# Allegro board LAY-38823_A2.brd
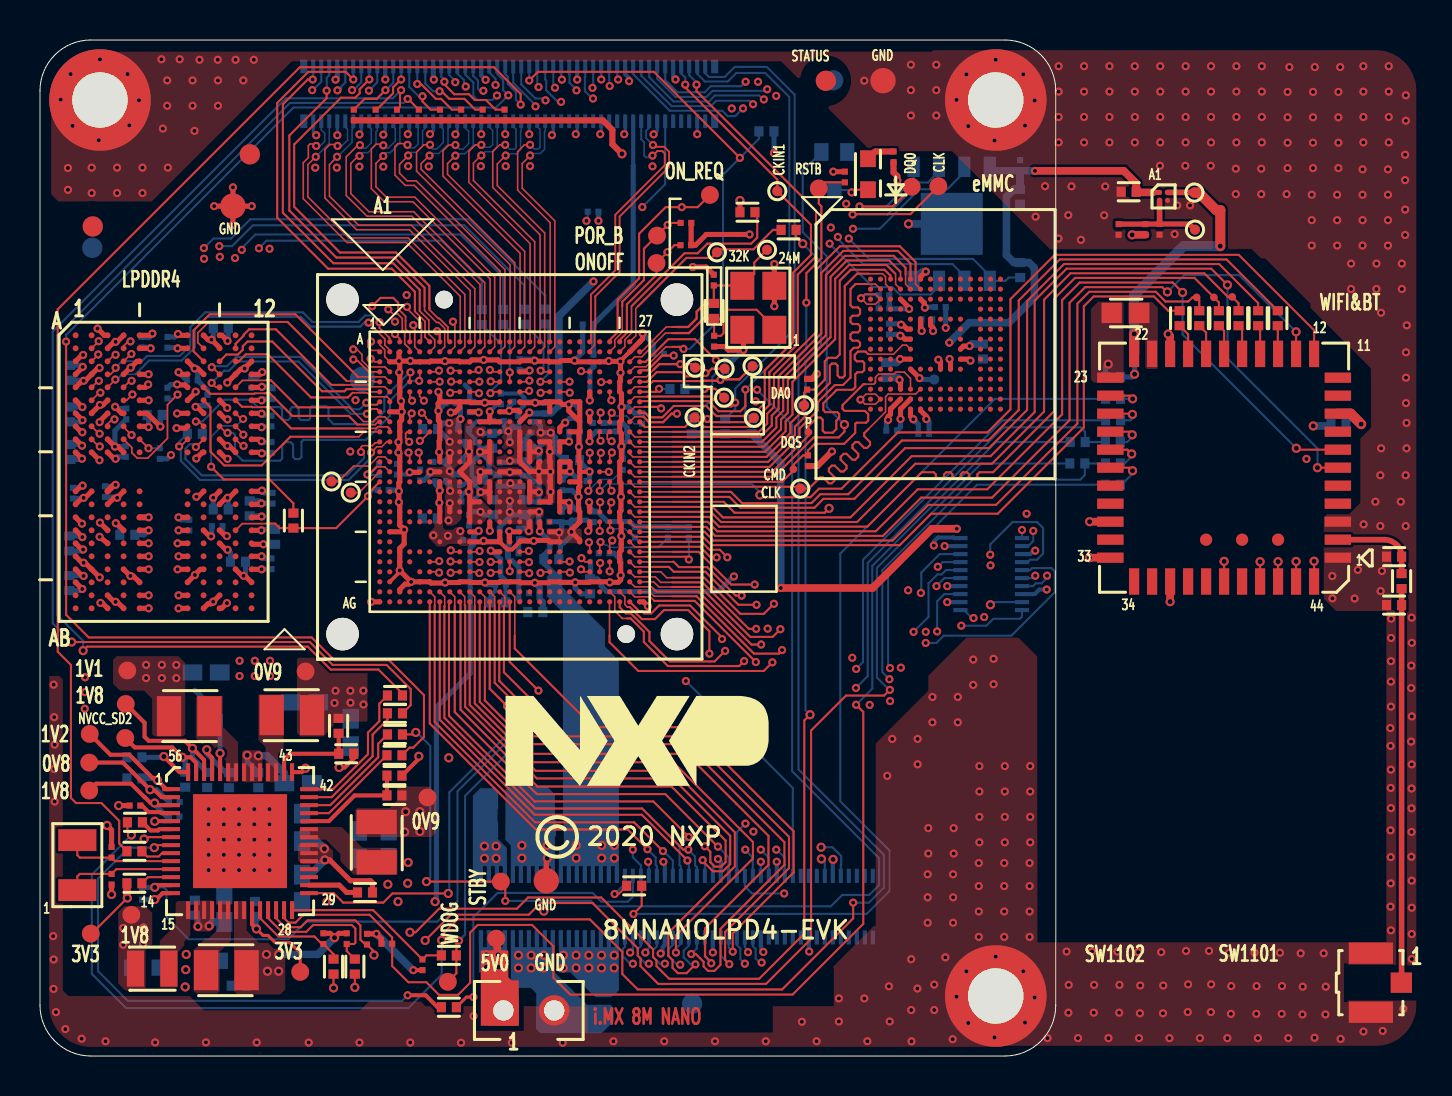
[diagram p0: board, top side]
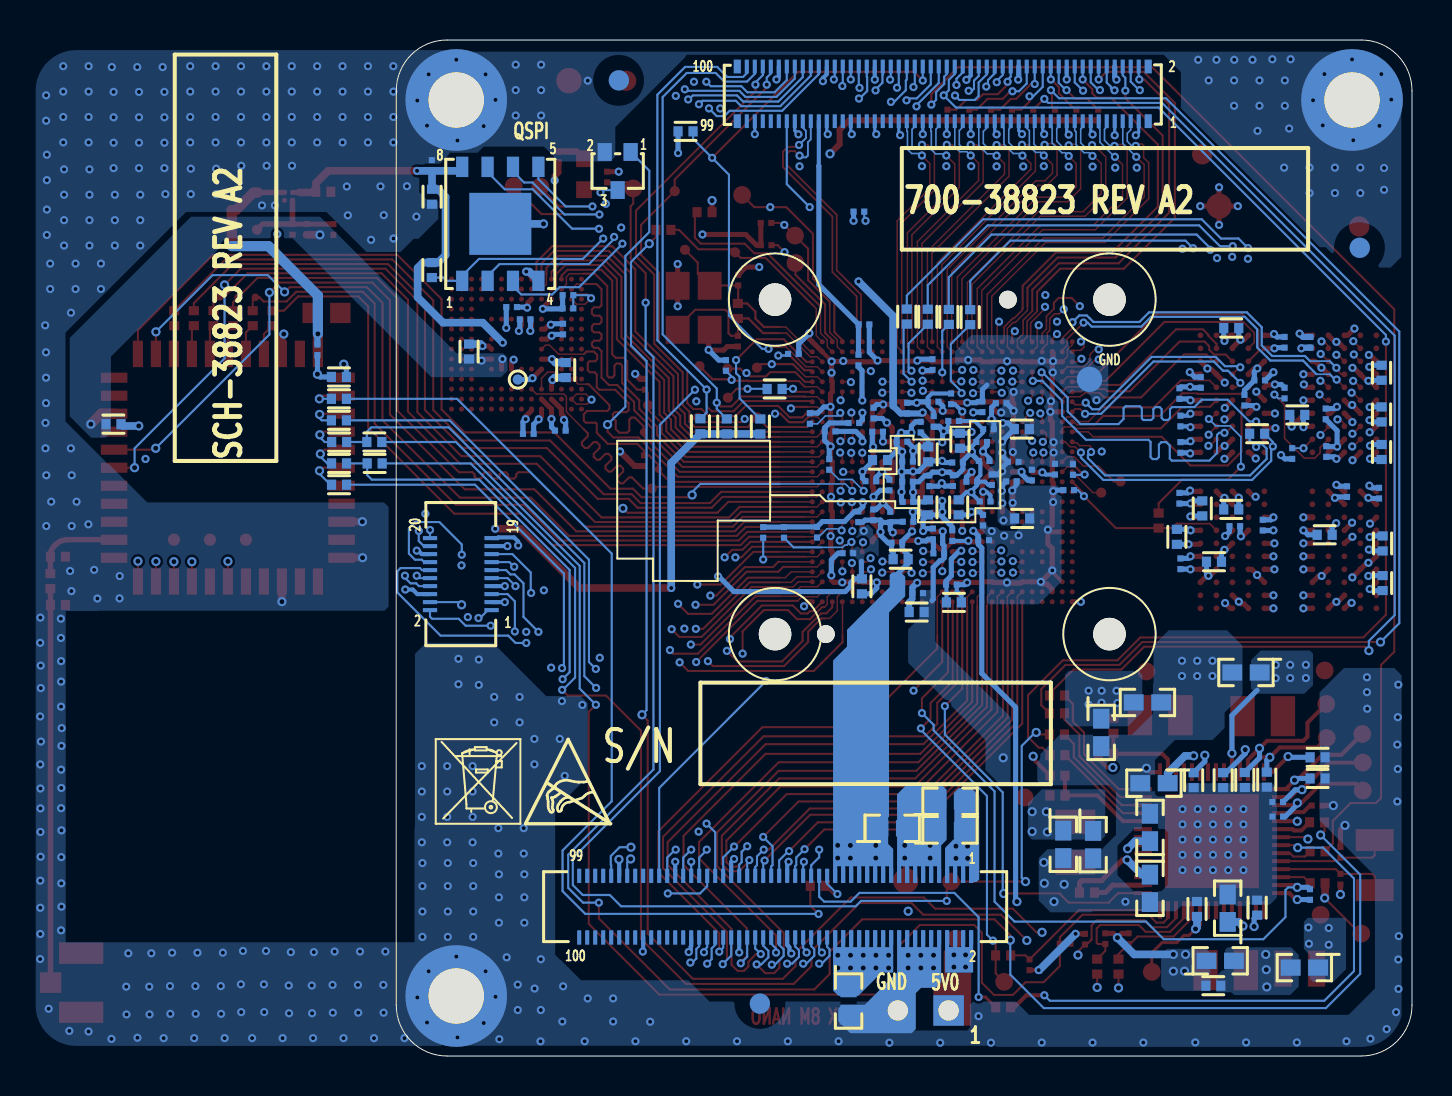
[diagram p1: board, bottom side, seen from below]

Outline 50.8 x 50.8 mm; copper layers: TOP, L2_GND, L3_IN1, L4_PWR_1, L5_PWR_2, BOTTOM. Coordinates in mm from the lower left corner of the outline.
Outline path: 0,48.26 0,2.54 arc(0.74,0.74) 2.54,0 48.26,0 arc(50.06,0.74) 50.8,2.54 50.8,48.26 arc(50.06,50.06) 48.26,50.8 2.54,50.8 arc(0.74,50.06) 0,48.26

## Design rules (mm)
constraint set DEFAULT: min track width 0.104
net group DDR-DATA0: nets DRAM_DQ06 DRAM_DQ07
net group DIFFPAIR5: nets USB1_DN USB1_DP
net group DIFFPAIR9: nets DSI_DN3 DSI_DP3
net group DIFFPAIR10: nets DSI_DN2 DSI_DP2
net group DIFFPAIR11: nets DSI_CKN DSI_CKP
net group DIFFPAIR12: nets DSI_DN1 DSI_DP1
net group DIFFPAIR13: nets DSI_DN0 DSI_DP0
net group DIFFPAIR19: nets CSI_DN0 CSI_DP0
net group DIFFPAIR20: nets CSI_DN1 CSI_DP1
net group DIFFPAIR21: nets CSI_CKN CSI_CKP
net group DIFFPAIR22: nets CSI_DN2 CSI_DP2
net group DIFFPAIR23: nets CSI_DN3 CSI_DP3
net group DDR-ADDRESS: nets DRAM_NRESET
net group M-DDR-DATA0: nets DRAM_DMI0 DRAM_DQ00 DRAM_DQ01 DRAM_DQ02 DRAM_DQ03 DRAM_DQ04 DRAM_DQ05 DRAM_SDQS0_C DRAM_SDQS0_T
net group M-DDR-DATA1: nets DRAM_DMI1 DRAM_DQ08 DRAM_DQ09 DRAM_DQ10 DRAM_DQ11 DRAM_DQ12 DRAM_DQ13 DRAM_DQ14 DRAM_DQ15 DRAM_SDQS1_C DRAM_SDQS1_T
net group M-EMMC: nets SD3_DATA1 SD3_DATA2 SD3_DATA3 SD3_DATA4 SD3_DATA5 SD3_DATA6 SD3_DATA7 SD3_STROBE
net group M-LPDDR-ADDRESS: nets DRAM_CA0_A DRAM_CA1_A DRAM_CA2_A DRAM_CA3_A DRAM_CA4_A DRAM_CA5_A DRAM_CK_C_A DRAM_CK_T_A DRAM_NCS0_A DRAM_NCS1_A
net group M-SD1: nets SD1_CLK SD1_CMD SD1_DATA0 SD1_DATA1 SD1_DATA2 SD1_DATA3
net group M-SD2: nets SD2_CLK SD2_CMD SD2_DATA0 SD2_DATA1 SD2_DATA2 SD2_DATA3

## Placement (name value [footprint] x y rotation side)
BH1  MOUNTING HOLE  [GNDPOINT256]  47.8 47.8 0 top
BH2  MOUNTING HOLE  [GNDPOINT256]  47.8 3 0 top
BH3  MOUNTING HOLE  [GNDPOINT256]  3 47.8 0 top
C1  0.22UF  [0201_CC]  22.93 31.75 180 bottom
C2  2.2uF  [0402_CC]  27.51 23.48 270 bottom
C3  0.22UF  [0201_CC]  26.94 27.06 270 bottom
C5  0.22UF  [0201_CC]  23.05 32.86 90 bottom
C6  0.22UF  [0201_CC]  25.76 25.66 0 bottom
C8  0.22UF  [0201_CC]  21.49 32.46 90 bottom
C9  0.22UF  [0201_CC]  29.11 31.23 0 bottom
C13  4.7uF  [0402_CC]  4.72 14.93 180 bottom
C15  1uF  [0201_CC]  25.21 27.71 180 bottom
C16  1uF  [0201_CC]  22.73 29.67 180 bottom
C17  0.22UF  [0201_CC]  27.69 26.96 270 bottom
C20  10uF  [0402_CC]  22.61 30.76 270 bottom
C21  0.22UF  [0201_CC]  23.04 23.57 180 bottom
C23  0.22UF  [0201_CC]  26.09 26.94 270 bottom
C30  0.22UF  [0201_CC]  26.93 32.15 90 bottom
C33  10uF  [0402_CC]  24.21 27.43 90 bottom
C35  1uF  [0201_CC]  22.96 28.77 90 bottom
C36  1uF  [0201_CC]  23.96 26.1 270 bottom
C48  1uF  [0201_CC]  21.45 26.79 270 bottom
C54  1uF  [0201_CC]  22.02 28.71 180 bottom
C55  10uF  [0402_CC]  22.67 27.43 90 bottom
C61  1uF  [0201_CC]  21.35 27.73 0 bottom
C65  1uF  [0201_CC]  23.92 31.73 90 bottom
C74  1uF  [0201_CC]  21.4 29.75 0 bottom
C78  1uF  [0201_CC]  21.52 30.7 0 bottom
C88  10uF  [0402_CC]  19.5 26.88 180 bottom
C89  10uF  [0402_CC]  19.51 31.35 180 bottom
C90  1uF  [0201_CC]  21.01 28.82 270 bottom
C91  1uF  [0201_CC]  19.01 29.05 90 bottom
C92  1uF  [0201_CC]  19.94 29.71 180 bottom
C93  1uF  [0201_CC]  20.03 28.73 180 bottom
C94  1uF  [0201_CC]  20.55 32.64 180 bottom
C95  1uF  [0201_CC]  21.18 31.34 0 bottom
C99  0.22UF  [0201_CC]  23.67 25.13 0 bottom
C100  0.22UF  [0201_CC]  23.95 32.71 0 bottom
C101  0.22UF  [0201_CC]  26.13 28.55 270 bottom
C104  0.22UF  [0201_CC]  27.07 28.74 0 bottom
C105  10uF  [0402_CC]  1.47 25.63 90 bottom
C106  10uF  [0402_CC]  11.76 25.96 90 bottom
C108  10uF  [0402_CC]  1.52 32.08 270 bottom
C109  10uF  [0402_CC]  4.37 26.06 0 bottom
C110  10uF  [0402_CC]  9.04 27.33 0 bottom
C111  10uF  [0402_CC]  9.9 24.71 0 bottom
C112  10uF  [0402_CC]  5.74 32.05 0 bottom
C113  10uF  [0402_CC]  10.49 27.38 90 bottom
C114  0.22UF  [0201_CC]  7.62 33.78 0 bottom
C115  10uF  [0402_CC]  1.52 30.2 90 bottom
C117  10uF  [0402_CC]  1.52 34.16 270 bottom
C118  10uF  [0402_CC]  9.04 36.4 0 bottom
C119  10uF  [0402_CC]  1.47 23.65 270 bottom
C121  4.7uF  [0402_CC]  64.94 31.59 180 bottom
C122  4.7uF  [0402_CC]  53.67 33.95 0 bottom
C123  12pF  [0201_CC]  33.7 38.79 90 top
C124  12pF  [0201_CC]  33.71 35.74 270 top
C127  4.7uF  [0402_CC]  47.16 35.22 90 bottom
C128  0.22UF  [0201_CC]  42.46 36.35 270 bottom
C129  0.22UF  [0201_CC]  44.35 36.83 0 bottom
C130  10uF  [0402_CC]  42.33 34.3 90 bottom
C131  0.22UF  [0201_CC]  45.03 37.45 0 bottom
C132  0.22UF  [0201_CC]  44.2 31.11 0 bottom
C133  0.22UF  [0201_CC]  42.59 31.27 0 bottom
C136  0.22UF  [0201_CC]  42.21 38.04 0 bottom
C137  1uF  [0201_CC]  42.21 37.38 0 bottom
C138  0.22UF  [0201_CC]  49.02 44.53 90 bottom
C139  10uF  [0402_CC]  49.01 42.96 270 bottom
C146  4.7uF  [0402_CC]  54.45 43.21 180 top
C148  0.22UF  [0201_CC]  55.99 41.33 270 top
C234  4.7uF  [0402_CC]  26.61 29.8 180 bottom
C235  0.22UF  [0201_CC]  25.51 30.71 180 bottom
C241  0.22UF  [0201_CC]  26.73 31.21 0 bottom
C244  0.22UF  [0201_CC]  25.25 32.39 90 bottom
C245  18pF  [0201_CC]  29.14 29.58 90 bottom
C247  10uF  [0402_CC]  24.2 30.08 90 bottom
C248  1uF  [0201_CC]  25.2 26.71 0 bottom
C251  1uF  [0201_CC]  22.99 26.02 270 bottom
C253  1uF  [0201_CC]  24.14 28.76 90 bottom
C254  1uF  [0201_CC]  25.23 29.72 180 bottom
C255  1uF  [0201_CC]  25.23 28.71 180 bottom
C256  1uF  [0201_CC]  24.57 31.44 270 bottom
C260  4.7uF  [0402_CC]  25.57 24.84 0 bottom
C264  0.22UF  [0201_CC]  21.42 25.79 180 bottom
C265  10uF  [0402_CC]  24.77 22.2 0 bottom
C266  10uF  [0402_CC]  22.91 22.68 180 bottom
C267  1uF  [0201_CC]  17.86 29.34 90 bottom
C268  2200PF  [0201_CC]  23.98 34.57 90 bottom
C272  1uF  [0402_CC]  9.45 13.79 270 bottom
C273  1.0UF  [0402_CC]  10.75 7.35 270 bottom
C274  1uF  [0201_CC]  4.75 12.52 0 top
C275  22uF  [CC0603]  13.23 17.68 180 bottom
C276  1.0UF  [0402_CC]  9.94 3.51 180 bottom
C279  10uF  [CC0603]  13.1 11.43 90 bottom
C281  10uF  [CC0603]  13.11 8.38 270 bottom
C283  22uF  [CC0603]  17.44 10.58 270 bottom
C285  22uF  [CC0603]  15.54 16.18 270 bottom
C287  22uF  [CC0603]  15.95 10.57 270 bottom
C295  10uF  [CC0603]  9.22 7.39 90 bottom
C298  18pF  [0201_CC]  3.58 10.18 90 top
C299  18pF  [0201_CC]  3.58 8.84 270 top
C301  10uF  [CC0603]  12.91 13.64 0 bottom
C302  4.7uF  [0402_CC]  7.75 7.42 90 bottom
C311  22uF  [CC0603]  9.59 4.76 180 bottom
C317  22uF  [CC0603]  5.38 4.42 0 bottom
C318  22uF  [CC0603]  8.3 19.18 0 bottom
C333  1uF  [0201_CC]  6.71 11.97 0 bottom
C337  1uF  [0201_CC]  6.72 12.7 0 bottom
C351  1uF  [0402_CC]  4.72 13.88 180 bottom
C363  2.2uF  [0402_CC]  8.36 13.8 270 bottom
C365  1uF  [0402_CC]  7.26 13.82 270 bottom
C370  0.22UF  [0201_CC]  8.86 26.49 0 bottom
C371  0.22UF  [0201_CC]  4.32 32.1 270 bottom
C372  0.22UF  [0201_CC]  11.63 33.12 90 bottom
C373  0.22UF  [0201_CC]  11.58 30.43 90 bottom
C374  0.22UF  [0201_CC]  11.58 24.61 90 bottom
C375  0.22UF  [0201_CC]  3.25 28.22 270 bottom
C376  0.22UF  [0201_CC]  4.29 30.23 90 bottom
C378  0.22UF  [0201_CC]  11.63 27.89 270 bottom
C379  0.22UF  [0201_CC]  11.58 31.75 90 bottom
C380  0.22UF  [0201_CC]  10.56 33.68 270 bottom
C381  0.22UF  [0201_CC]  1.65 28.14 270 bottom
C382  0.22UF  [0201_CC]  7.47 26.54 270 bottom
C384  0.22UF  [0201_CC]  8.38 32.79 90 bottom
C391  1uF  [0201_CC]  27.91 31.65 0 bottom
C392  0.22UF  [0201_CC]  28.21 25.14 0 bottom
C393  0.22UF  [0201_CC]  27.41 36.58 180 bottom
C400  0.22UF  [0201_CC]  24.72 23.14 0 bottom
C401  10uF  [CC0603]  23.1 12.74 180 bottom
C402  10uF  [CC0603]  23.1 11.3 180 bottom
C403  22uF  [CC0603]  26 11.39 180 bottom
C404  22uF  [CC0603]  28.18 2.75 270 bottom
C453  4.7uF  [0402_CC]  10.92 13.79 270 bottom
C454  1uF  [0201_CC]  54.74 35.31 270 bottom
C455  10pF  [0402_CC]  68.1 23.74 270 top
C456  10pF  [0402_CC]  67.72 24.97 180 top
C457  10pF  [0402_CC]  67.72 22.54 180 top
D1  LED GREEN  [LED_0603]  41.41 44.09 270 top
J1  MXC3N2001  [CON_3_UFL_R_SMT]  66.56 3.67 270 top
J4  DF40C-100DP-0.4V(51)  [CON100_0P4_21P7X2P05_SM]  23.47 48.11 0 bottom
J5  DF40C-100DS-0.4V(51)  [CON100_0P4_22P8X3P1_SM]  31.85 7.47 0 bottom
J6  HDR 1X2 TH  [HDR_1X2]  23.18 2.28 90 top
J7  DF40C-20DS-0.4V(51)  [CON20_0P4_6P8X3P1_SM]  47.57 24.1 90 bottom
L1  2.2uH  [IND_0603A]  54.29 37.15 180 top
L5  0.47uH  [IND_SPH2520]  12.6 17.04 0 top
L6  0.47uH  [IND_SPH2520]  16.84 10.69 90 top
L11  0.47uH  [IND_SPH2520]  9.32 4.29 0 top
L13  0.47uH  [IND_2016A]  5.61 4.37 180 top
L15  0.47uH  [IND_SPH2520]  7.47 16.99 180 top
NOREF  -  []  7.41 7.29 0 top
NOREF#2  -  []  1.78 22.38 0 top
NOREF#3  -  []  23.3 13.51 0 top
NOREF#4  -  [unnamed#2]  2.64 41.48 0 top
NOREF#5  -  []  -264.82 291.64 0 top
NOREF#6  -  []  53.53 24.92 90 top
NOREF#7  -  []  6.51 0.24 0 top
NOREF#8  -  []  11.23 21.91 90 top
NOREF#9  -  []  46.03 25.9 0 top
NOREF#10  -  []  27.36 2.21 0 top
NOREF#11  -  []  641.81 -152.03 0 top
NOREF#12  -  []  54.72 35.11 0 top
NOREF#13  -  [unnamed#2]  39.3 48.76 0 top
NOREF#14  -  []  23.49 29.21 0 top
NOREF#15  -  []  38.33 6.17 0 top
NOREF#16  -  []  22.05 9.01 0 top
NOREF#17  -  []  10.58 35.38 90 top
NOREF#18  -  []  1.13 21.91 0 top
NOREF#19  -  []  56.39 42.78 90 top
NOREF#20  -  []  12.61 7.29 90 top
NOREF#21  -  []  54.72 35.11 0 top
NOREF#22  -  []  55.99 42.78 0 top
NOREF#23  -  []  1.78 22.38 0 top
NOREF#24  -  []  -292.82 -210.12 0 top
NOREF#25  -  []  53.53 33.92 0 top
NOREF#26  -  []  279.89 66.11 0 top
NOREF#27  -  []  25.87 10.93 0 top
NOREF#28  -  []  53.17 35.47 0 top
NOREF#29  -  [unnamed#2]  10.49 45.08 90 top
NOREF#30  -  []  46.03 22.3 90 top
NOREF#31  -  []  46.03 22.3 90 top
NOREF#32  -  []  22.85 9.01 0 top
NOREF#33  -  []  10.58 22.38 90 top
NOREF#34  -  []  13.46 8.14 90 top
NOREF#35  -  []  -25.43 -42.54 0 top
NOREF#36  -  []  53.53 33.02 90 top
NOREF#37  -  []  -38.84 -146.35 0 top
NOREF#38  -  []  59.22 29.42 0 top
NOREF#39  -  []  56.59 42.58 90 top
NOREF#40  -  []  43.25 5.9 90 top
NOREF#41  -  []  6.56 8.14 0 top
NOREF#42  -  []  46 27.5 0 top
NOREF#43  -  []  55.79 42.58 0 top
NOREF#44  -  []  6.51 0.24 90 top
NOREF#45  -  []  46 20.7 90 top
NOREF#46  -  []  53.17 23.37 90 top
NOREF#47  -  []  20.45 9.04 0 top
NOREF#48  -  []  41.65 5.93 90 top
NOREF#49  -  []  54.72 23.73 90 top
NOREF#50  -  [unnamed#3]  23.49 29.46 270 top
NOREF#51  -  []  13.46 12.94 90 top
NOREF#52  -  []  0.16 0.59 0 top
NOREF#53  -  []  58.32 25.82 0 top
NOREF#54  -  []  -8.88 -33.57 0 top
NOREF#55  -  []  58.32 25.82 90 top
NOREF#56  -  []  59.22 29.42 0 top
NOREF#57  -  []  41.62 6.72 90 top
NOREF#58  -  []  7.41 7.29 0 top
NOREF#59  -  [unnamed#2]  2.61 40.41 180 bottom
NOREF#60  -  [unnamed#2]  39.67 48.78 180 bottom
NOREF#61  -  [unnamed#2]  32.61 2.62 270 bottom
Q1  NX3008NBKW,115  [SC70_3]  39.73 44.25 0 bottom
QZ2  32.768KHZ  [XTAL2-3P2X1P5-SM]  1.87 9.54 90 top
R4  10K  [0201_CC]  17.17 28.29 180 bottom
R5  240 OHM  [0201_CC]  5.08 35.69 90 bottom
R7  240 OHM  [0201_CC]  16.96 29.32 270 bottom
R8  150  [0402_CC]  7.75 31.11 0 bottom
R10  4.7K  [0201_CC]  17.85 47.05 90 top
R11  4.7K  [0201_CC]  18.95 47.05 90 top
R12  4.7K  [0201_CC]  15.69 47.05 90 top
R13  4.7K  [0201_CC]  16.79 47.05 90 top
R14  4.7K  [0201_CC]  20.01 47.05 90 top
R15  4.7K  [0201_CC]  21.06 47.05 90 top
R16  4.7K  [0201_CC]  22.14 47.05 90 top
R17  4.7K  [0201_CC]  23.23 47.05 90 top
R18  10K  [0201_CC]  34.31 34.53 90 bottom
R20  100K  [0201_CC]  32.31 41.66 180 top
R21  100K  [0201_CC]  32.3 40.54 180 top
R23  10K  [0201_CC]  30.94 35.1 180 bottom
R26  510K  [0402_CC]  33.71 37.25 270 top
R27  50 OHM  [0402_CC]  31.88 33.35 0 bottom
R29  200  [0201_CC]  27.66 42.22 0 bottom
R37  10K  [0402_CC]  49.02 39.3 270 bottom
R47  10K  [0402_CC]  34.27 31.48 270 bottom
R48  0  [0402_CC]  17.75 17.13 180 top
R51  0  [0402_CC]  17.73 15.04 180 top
R52  0  [0402_CC]  17.75 16.08 180 top
R54  0  [0402_CC]  17.75 18.02 180 top
R55  0  [0402_CC]  20.45 5.03 180 top
R61  100K  [0201_CC]  5.1 8.08 270 bottom
R77  10K  [0402_CC]  36.33 46.23 0 bottom
R78  10K  [0402_CC]  32.59 31.48 270 bottom
R79  10K  [0402_CC]  35.59 31.49 270 bottom
R100  0  [0402_CC]  37.44 41.31 180 top
R102  100K  [0201_CC]  40.25 43.95 270 top
R103  100K  [0201_CC]  30.11 31.88 90 bottom
R106  100K  [0201_CC]  19.13 4.56 90 top
R108  30K  [0201_CC]  27.68 34.8 90 bottom
R111  0  [0402_CC]  4.75 11.68 180 top
R113  0  [0402_CC]  35.38 42.19 0 top
R114  0  [0402_CC]  4.72 10.24 180 top
R115  0  [0402_CC]  53.67 32.86 0 bottom
R116  0  [0402_CC]  29.72 8.51 180 top
R117  10K  [0201_CC]  38.36 33.59 270 top
R118  10K  [0201_CC]  38.41 29.76 90 top
R119  10K  [0201_CC]  31.41 26.18 270 bottom
R120  10K  [0201_CC]  29.76 26.19 270 bottom
R121  10K  [0201_CC]  6.37 33.15 270 bottom
R125  1K  [0201_CC]  42.69 44.96 90 top
R127  0  [0402_CC]  20.45 2.44 180 top
R129  0  [0402_CC]  53.66 28.56 180 bottom
R130  0  [0402_CC]  53.66 29.63 180 bottom
R131  0  [0402_CC]  53.66 30.7 180 bottom
R132  0  [0402_CC]  53.67 31.78 180 bottom
R133  4.7K  [0201_CC]  32.45 26.18 270 bottom
R137  0  [0402_CC]  4.72 8.64 0 top
R153  10K  [0201_CC]  55.28 41.33 90 top
R157  240 OHM  [0201_CC]  6.37 35.69 90 bottom
R158  10K  [0201_CC]  5.99 30.12 90 bottom
R191  0  [0402_CC]  15.31 15.11 0 top
R192  0  [0402_CC]  14.93 16.51 270 top
R193  0  [0402_CC]  17.73 13.03 180 top
R194  0  [0402_CC]  17.73 14.02 0 top
R195  0  [0402_CC]  16.25 8.18 0 top
R196  4.7K  [0201_CC]  17.35 5.61 0 top
R197  4.7K  [0201_CC]  16.36 5.84 270 top
R198  0  [0402_CC]  51.89 30.7 180 bottom
R199  0  [0402_CC]  51.88 29.63 180 bottom
R200  4.7K  [0201_CC]  14.17 5.87 270 top
R201  4.7K  [0201_CC]  15.34 5.87 270 top
R202  0  [0402_CC]  14.68 4.47 90 top
R203  0  [0402_CC]  15.75 4.47 90 top
R204  0  [0402_CC]  12.67 26.77 270 top
R205  0  [0402_CC]  25.27 36.97 270 bottom
R206  0  [0402_CC]  22.1 36.94 270 bottom
R207  0  [0402_CC]  23.16 36.95 270 bottom
R208  0  [0402_CC]  24.22 36.96 270 bottom
R209  0  [0402_CC]  57.98 36.89 270 top
R210  0  [0402_CC]  57 36.89 270 top
R211  0  [0402_CC]  61.91 36.89 270 top
R212  0  [0402_CC]  60.92 36.89 270 top
R213  0  [0402_CC]  59.94 36.89 270 top
R214  0  [0402_CC]  58.96 36.89 270 top
R215  12K  [0201_CC]  53.94 41.33 270 top
TP2  -  [TPAD_020]  34.24 34.37 0 top
TP3  -  [TPAD_020]  34.21 32.92 0 top
TP4  -  [TPAD_020]  35.63 34.49 0 top
TP5  -  [TPAD_020]  32.76 34.42 0 top
TP6  TP_35MIL  [TESTPOINT_35MIL]  33.5 43.05 0 top
TP7  TP_35MIL  [TESTPOINT_35MIL]  30.83 39.65 180 top
TP8  TP_35MIL  [TESTPOINT_35MIL]  38.95 43.38 270 top
TP9  TP_35MIL  [TESTPOINT_35MIL]  30.86 41.02 0 top
TP10  TP_35MIL  [TESTPOINT_35MIL]  23.05 8.72 0 top
TP12  -  [TPAD_020]  57.76 41.32 0 top
TP13  -  [TPAD_020]  57.73 43.17 0 top
TP15  -  [TPAD_020]  14.58 28.73 0 top
TP16  TP_35MIL  [TESTPOINT_35MIL]  43.59 43.46 180 top
TP17  TP_35MIL  [TESTPOINT_35MIL]  44.93 43.49 180 top
TP18  -  [TPAD_020]  44.72 33.82 180 bottom
TP19  -  [TPAD_020]  35.7 31.91 0 top
TP20  -  [TPAD_020]  36.87 43.24 0 top
TP21  -  [TPAD_020]  32.74 31.93 0 top
TP22  TP_35MIL  [TESTPOINT_35MIL]  13.28 19.23 0 top
TP23  TP_35MIL  [TESTPOINT_35MIL]  19.38 12.93 90 top
TP24  -  [TPAD_015]  57.84 37.93 180 top
TP25  TP_35MIL  [TESTPOINT_35MIL]  2.54 6.12 0 top
TP26  TP_35MIL  [TESTPOINT_35MIL]  4.57 7.06 0 top
TP27  TP_35MIL  [TESTPOINT_35MIL]  4.37 19.28 270 top
TP28  TP_35MIL  [TESTPOINT_35MIL]  2.46 13.27 0 top
TP29  TP_35MIL  [TESTPOINT_35MIL]  2.46 14.67 0 top
TP31  TP_35MIL  [TESTPOINT_35MIL]  2.49 16.1 0 top
TP32  TP_35MIL  [TESTPOINT_35MIL]  4.29 17.6 0 top
TP33  TP_35MIL  [TESTPOINT_35MIL]  4.27 15.9 0 top
TP34  -  [TPAD_020]  38.02 28.37 0 top
TP35  -  [TPAD_015]  37.68 29.34 0 top
TP36  -  [TPAD_020]  38.21 32.54 0 top
TP38  -  [TPAD_020]  36.36 40.31 0 top
TP39  -  [TPAD_020]  33.85 40.18 0 top
TP40  -  [TPAD_015]  38.43 31.19 0 top
TP44  -  [TPAD_050]  9.65 42.49 0 top
TP45  -  [TPAD_050]  25.32 8.76 0 top
TP46  -  [TPAD_050]  42.16 48.77 0 top
TP47  -  [TPAD_050]  16.13 33.83 180 bottom
TP51  TP_35MIL  [TESTPOINT_35MIL]  22.82 5.87 0 top
TP53  TP_35MIL  [TESTPOINT_35MIL]  20.4 3.71 0 top
TP58  -  [TPAD_020]  15.54 28.17 0 top
TP66  -  [TPAD_015]  58.71 37.93 180 top
TP67  -  [TPAD_015]  59.62 37.96 180 top
TP68  TP_35MIL  [TESTPOINT_35MIL]  13.01 4.21 0 top
U1  MIMX8MN6DVTJZAA  [BGA486_0P5_14X14]  23.49 29.21 0 top
U2  -  [BGA200_0P65X0P8_10P1X14P6]  6.18 29.21 0 top
U4  SDINBDG4-32G-I1  [FBGA153_0P5_11P5X13]  44.79 35.59 0 top
U5  MT25QU256ABA1EW7-0SIT  [DFN8_1P27_6X5MM_3P1]  45.6 41.61 90 bottom
U7  ADP191ACBZ-R7  [WLCSP4_0P4_0P8X0P8_SMDP]  56.19 42.98 0 top
U8  PCA9450BHN  [HVQFN56_0P4_7X7_EP4P7MM]  10.01 10.74 0 top
U9  AW-CM358SM  [MODULE_WIFI_0P9_12X12_47PIN_A]  59.22 29.42 180 top
Y1  24MHZ  [XTLOSC4_3P2X2P5MM_SM]  35.93 37.41 90 top

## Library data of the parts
BH1-BH3 = MOUNT_HOLE
C1-C3 C5 C6 C8 C9 C13 C15-C17 C20 C21 C23 C30 C33 C35 C36 C48 C54 C55 C61 C65 C74 C78 C88-C95 C99-C101 C104-C106 C108-C115 C117-C119 C121-C124 C127-C133 C136-C139 C146 C148 C234 C235 C241 C244 C245 C247 C248 C251 C253-C256 C260 C264-C268 C272-C276 C279 C281 C283 C285 C287 C295 C298 C299 C301 C302 C311 C317 C318 C333 C337 C351 C363 C365 C370-C376 C378-C382 C384 C391-C393 C400-C404 C453-C457 = CAP_NP
D1 = LED
J1 = UFL
J4 J5 = HDR_2X50_M
J6 = CONN_HDR_2X1
J7 = CONN_HDR_10X2
L1 L13 = INDUCTOR
L5 L6 L11 L15 = INDUCTOR: tolerance: 20%
Q1 = NMOS_NX3008NBK
QZ2 = XTAL
R4 R5 R7 R8 R10-R18 R20 R21 R23 R26 R27 R29 R37 R48 R51 R52 R54 R55 R61 R100 R102 R103 R106 R108 R113-R121 R125 R127 R133 R137 R153 R157 R158 R191-R203 R215 = RES
R47 R77-R79 = RES: tolerance: 5%
R111 R129-R132 R204-R214 = RES: tolerance: 1%
TP2-TP5 TP12 TP13 TP15 TP18-TP21 TP24 TP34-TP36 TP38-TP40 TP44-TP47 TP58 TP66 TP67 = TESTLOOP
TP6-TP10 TP16 TP17 TP22 TP23 TP25-TP29 TP31-TP33 TP51 TP53 TP68 = T POINT R: Tolerance: TOLERANCE; User Part Number: 510-75618
U1 = MIMX8NN_BGA486P
U2 = C1612PC2WDGTKR-U_BGA200P
U4 = SDINBDG4-16G_VFBGA_153P
U5 = MT25QL256ABA1EW9_9P
U7 = ADP199_4P
U8 = PCA9450_HVQFN56P_A
U9 = AW_CM358SM
Y1 = XTAL_13

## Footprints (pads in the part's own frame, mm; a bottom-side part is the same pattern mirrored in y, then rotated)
0201_CC
  rect 0.305x0.305 smd: 1(-0.267,0) 2(0.267,0)
0402_CC
  rect 0.457x0.508 smd: 1(-0.375,0) 2(0.375,0)
BGA200_0P65X0P8_10P1X14P6
  round 0.292 smd: A1(-4.4,6.825) A2(-3.6,6.825) A3(-2.8,6.825) A4(-2,6.825) A5(-1.2,6.825) A8(1.2,6.825) A9(2,6.825) A10(2.8,6.825) A11(3.6,6.825) A12(4.4,6.825) AA1(-4.4,-6.175) AA2(-3.6,-6.175) AA3(-2.8,-6.175) AA4(-2,-6.175) AA5(-1.2,-6.175) AA8(1.2,-6.175) AA9(2,-6.175) AA10(2.8,-6.175) AA11(3.6,-6.175) AA12(4.4,-6.175) AB1(-4.4,-6.825) AB2(-3.6,-6.825) AB3(-2.8,-6.825) AB4(-2,-6.825) AB5(-1.2,-6.825) AB8(1.2,-6.825) AB9(2,-6.825) AB10(2.8,-6.825) AB11(3.6,-6.825) AB12(4.4,-6.825) B1(-4.4,6.175) B2(-3.6,6.175) B3(-2.8,6.175) B4(-2,6.175) B5(-1.2,6.175) B8(1.2,6.175) B9(2,6.175) B10(2.8,6.175) B11(3.6,6.175) B12(4.4,6.175) C1(-4.4,5.525) C2(-3.6,5.525) C3(-2.8,5.525) C4(-2,5.525) C5(-1.2,5.525) C8(1.2,5.525) C9(2,5.525) C10(2.8,5.525) C11(3.6,5.525) C12(4.4,5.525) D1(-4.4,4.875) D2(-3.6,4.875) D3(-2.8,4.875) D4(-2,4.875) D5(-1.2,4.875) D8(1.2,4.875) D9(2,4.875) D10(2.8,4.875) D11(3.6,4.875) D12(4.4,4.875) E1(-4.4,4.225) E2(-3.6,4.225) E3(-2.8,4.225) E4(-2,4.225) E5(-1.2,4.225) E8(1.2,4.225) E9(2,4.225) E10(2.8,4.225) E11(3.6,4.225) E12(4.4,4.225) F1(-4.4,3.575) F2(-3.6,3.575) F3(-2.8,3.575) F4(-2,3.575) F5(-1.2,3.575) F8(1.2,3.575) F9(2,3.575) F10(2.8,3.575) F11(3.6,3.575) F12(4.4,3.575) G1(-4.4,2.925) G2(-3.6,2.925) G3(-2.8,2.925) G4(-2,2.925) G5(-1.2,2.925) G8(1.2,2.925) G9(2,2.925) G10(2.8,2.925) G11(3.6,2.925) G12(4.4,2.925) H1(-4.4,2.275) H2(-3.6,2.275) H3(-2.8,2.275) H4(-2,2.275) H5(-1.2,2.275) H8(1.2,2.275) H9(2,2.275) H10(2.8,2.275) H11(3.6,2.275) H12(4.4,2.275) J1(-4.4,1.625) J2(-3.6,1.625) J3(-2.8,1.625) J4(-2,1.625) J5(-1.2,1.625) J8(1.2,1.625) J9(2,1.625) J10(2.8,1.625) J11(3.6,1.625) J12(4.4,1.625) K1(-4.4,0.975) K2(-3.6,0.975) K3(-2.8,0.975) K4(-2,0.975) K5(-1.2,0.975) K8(1.2,0.975) K9(2,0.975) K10(2.8,0.975) K11(3.6,0.975) K12(4.4,0.975) N1(-4.4,-0.975) N2(-3.6,-0.975) N3(-2.8,-0.975) N4(-2,-0.975) N5(-1.2,-0.975) N8(1.2,-0.975) N9(2,-0.975) N10(2.8,-0.975) N11(3.6,-0.975) N12(4.4,-0.975) P1(-4.4,-1.625) P2(-3.6,-1.625) P3(-2.8,-1.625) P4(-2,-1.625) P5(-1.2,-1.625) P8(1.2,-1.625) P9(2,-1.625) P10(2.8,-1.625) P11(3.6,-1.625) P12(4.4,-1.625) R1(-4.4,-2.275) R2(-3.6,-2.275) R3(-2.8,-2.275) R4(-2,-2.275) R5(-1.2,-2.275) R8(1.2,-2.275) R9(2,-2.275) R10(2.8,-2.275) R11(3.6,-2.275) R12(4.4,-2.275) T1(-4.4,-2.925) T2(-3.6,-2.925) T3(-2.8,-2.925) T4(-2,-2.925) T5(-1.2,-2.925) T8(1.2,-2.925) T9(2,-2.925) T10(2.8,-2.925) T11(3.6,-2.925) T12(4.4,-2.925) U1(-4.4,-3.575) U2(-3.6,-3.575) U3(-2.8,-3.575) U4(-2,-3.575) U5(-1.2,-3.575) U8(1.2,-3.575) U9(2,-3.575) U10(2.8,-3.575) U11(3.6,-3.575) U12(4.4,-3.575) V1(-4.4,-4.225) V2(-3.6,-4.225) V3(-2.8,-4.225) V4(-2,-4.225) V5(-1.2,-4.225) V8(1.2,-4.225) V9(2,-4.225) V10(2.8,-4.225) V11(3.6,-4.225) V12(4.4,-4.225) W1(-4.4,-4.875) W2(-3.6,-4.875) W3(-2.8,-4.875) W4(-2,-4.875) W5(-1.2,-4.875) W8(1.2,-4.875) W9(2,-4.875) W10(2.8,-4.875) W11(3.6,-4.875) W12(4.4,-4.875) Y1(-4.4,-5.525) Y2(-3.6,-5.525) Y3(-2.8,-5.525) Y4(-2,-5.525) Y5(-1.2,-5.525) Y8(1.2,-5.525) Y9(2,-5.525) Y10(2.8,-5.525) Y11(3.6,-5.525) Y12(4.4,-5.525)
BGA486_0P5_14X14
  round 0.254 smd: A1(-6.5,6.5) A2(-6,6.5) A3(-5.5,6.5) A4(-5,6.5) A5(-4.5,6.5) A6(-4,6.5) A7(-3.5,6.5) A8(-3,6.5) A9(-2.5,6.5) A10(-2,6.5) A11(-1.5,6.5) A12(-1,6.5) A13(-0.5,6.5) A14(0,6.5) A15(0.5,6.5) A16(1,6.5) A17(1.5,6.5) A18(2,6.5) A19(2.5,6.5) A20(3,6.5) A21(3.5,6.5) A22(4,6.5) A23(4.5,6.5) A24(5,6.5) A25(5.5,6.5) A26(6,6.5) A27(6.5,6.5) AA1(-6.5,-3.5) AA2(-6,-3.5) AA7(-3.5,-3.5) AA9(-2.5,-3.5) AA10(-2,-3.5) AA13(-0.5,-3.5) AA14(0,-3.5) AA15(0.5,-3.5) AA18(2,-3.5) AA19(2.5,-3.5) AA21(3.5,-3.5) AA26(6,-3.5) AA27(6.5,-3.5) AB1(-6.5,-4) AB2(-6,-4) AB3(-5.5,-4) AB4(-5,-4) AB5(-4.5,-4) AB6(-4,-4) AB9(-2.5,-4) AB10(-2,-4) AB13(-0.5,-4) AB15(0.5,-4) AB18(2,-4) AB19(2.5,-4) AB22(4,-4) AB23(4.5,-4) AB24(5,-4) AB25(5.5,-4) AB26(6,-4) AB27(6.5,-4) AC1(-6.5,-4.5) AC2(-6,-4.5) AC3(-5.5,-4.5) AC4(-5,-4.5) AC6(-4,-4.5) AC9(-2.5,-4.5) AC10(-2,-4.5) AC13(-0.5,-4.5) AC14(0,-4.5) AC15(0.5,-4.5) AC18(2,-4.5) AC19(2.5,-4.5) AC22(4,-4.5) AC24(5,-4.5) AC25(5.5,-4.5) AC26(6,-4.5) AC27(6.5,-4.5) AD1(-6.5,-5) AD2(-6,-5) AD5(-4.5,-5) AD6(-4,-5) AD9(-2.5,-5) AD10(-2,-5) AD13(-0.5,-5) AD15(0.5,-5) AD18(2,-5) AD19(2.5,-5) AD22(4,-5) AD23(4.5,-5) AD26(6,-5) AD27(6.5,-5) AE1(-6.5,-5.5) AE2(-6,-5.5) AE5(-4.5,-5.5) AE6(-4,-5.5) AE9(-2.5,-5.5) AE10(-2,-5.5) AE13(-0.5,-5.5) AE14(0,-5.5) AE15(0.5,-5.5) AE18(2,-5.5) AE19(2.5,-5.5) AE22(4,-5.5) AE23(4.5,-5.5) AE26(6,-5.5) AE27(6.5,-5.5) AF1(-6.5,-6) AF2(-6,-6) AF3(-5.5,-6) AF4(-5,-6) AF5(-4.5,-6) AF6(-4,-6) AF7(-3.5,-6) AF8(-3,-6) AF9(-2.5,-6) AF10(-2,-6) AF11(-1.5,-6) AF12(-1,-6) AF13(-0.5,-6) AF14(0,-6) AF15(0.5,-6) AF16(1,-6) AF17(1.5,-6) AF18(2,-6) AF19(2.5,-6) AF20(3,-6) AF21(3.5,-6) AF22(4,-6) AF23(4.5,-6) AF24(5,-6) AF25(5.5,-6) AF26(6,-6) AF27(6.5,-6) AG1(-6.5,-6.5) AG2(-6,-6.5) AG3(-5.5,-6.5) AG4(-5,-6.5) AG5(-4.5,-6.5) AG6(-4,-6.5) AG7(-3.5,-6.5) AG8(-3,-6.5) AG9(-2.5,-6.5) AG10(-2,-6.5) AG11(-1.5,-6.5) AG12(-1,-6.5) AG13(-0.5,-6.5) AG14(0,-6.5) AG15(0.5,-6.5) AG16(1,-6.5) AG17(1.5,-6.5) AG18(2,-6.5) AG19(2.5,-6.5) AG20(3,-6.5) AG21(3.5,-6.5) AG22(4,-6.5) AG23(4.5,-6.5) AG24(5,-6.5) AG25(5.5,-6.5) AG26(6,-6.5) AG27(6.5,-6.5) B1(-6.5,6) B2(-6,6) B3(-5.5,6) B4(-5,6) B5(-4.5,6) B6(-4,6) B7(-3.5,6) B8(-3,6) B9(-2.5,6) B10(-2,6) B11(-1.5,6) B12(-1,6) B13(-0.5,6) B14(0,6) B15(0.5,6) B16(1,6) B17(1.5,6) B18(2,6) B19(2.5,6) B20(3,6) B21(3.5,6) B22(4,6) B23(4.5,6) B24(5,6) B25(5.5,6) B26(6,6) B27(6.5,6) C1(-6.5,5.5) C2(-6,5.5) C5(-4.5,5.5) C6(-4,5.5) C9(-2.5,5.5) C10(-2,5.5) C13(-0.5,5.5) C14(0,5.5) C15(0.5,5.5) C18(2,5.5) C19(2.5,5.5) C22(4,5.5) C23(4.5,5.5) C26(6,5.5) C27(6.5,5.5) D1(-6.5,5) D2(-6,5) D5(-4.5,5) D6(-4,5) D9(-2.5,5) D10(-2,5) D13(-0.5,5) D15(0.5,5) D18(2,5) D19(2.5,5) D22(4,5) D23(4.5,5) D26(6,5) D27(6.5,5) E1(-6.5,4.5) E2(-6,4.5) E3(-5.5,4.5) E4(-5,4.5) E6(-4,4.5) E9(-2.5,4.5) E10(-2,4.5) E13(-0.5,4.5) E14(0,4.5) E15(0.5,4.5) E18(2,4.5) E19(2.5,4.5) E22(4,4.5) E24(5,4.5) E25(5.5,4.5) E26(6,4.5) E27(6.5,4.5) F1(-6.5,4) F2(-6,4) F3(-5.5,4) F4(-5,4) F5(-4.5,4) F6(-4,4) F9(-2.5,4) F10(-2,4) F13(-0.5,4) F15(0.5,4) F18(2,4) F19(2.5,4) F22(4,4) F23(4.5,4) F24(5,4) F25(5.5,4) F26(6,4) F27(6.5,4) G1(-6.5,3.5) G2(-6,3.5) G7(-3.5,3.5) G9(-2.5,3.5) G10(-2,3.5) G13(-0.5,3.5) G14(0,3.5) G15(0.5,3.5) G18(2,3.5) G19(2.5,3.5) G21(3.5,3.5) G26(6,3.5) G27(6.5,3.5) H1(-6.5,3) H2(-6,3) H10(-2,3) H13(-0.5,3) H15(0.5,3) H18(2,3) H26(6,3) H27(6.5,3) J1(-6.5,2.5) J2(-6,2.5) J3(-5.5,2.5) J4(-5,2.5) J5(-4.5,2.5) J6(-4,2.5) J7(-3.5,2.5) J10(-2,2.5) J11(-1.5,2.5) J12(-1,2.5) J13(-0.5,2.5) J14(0,2.5) J15(0.5,2.5) J16(1,2.5) J17(1.5,2.5) J18(2,2.5) J21(3.5,2.5) J22(4,2.5) J23(4.5,2.5) J24(5,2.5) J25(5.5,2.5) J26(6,2.5) J27(6.5,2.5) K1(-6.5,2) K2(-6,2) K3(-5.5,2) K4(-5,2) K5(-4.5,2) K6(-4,2) K7(-3.5,2) K8(-3,2) K9(-2.5,2) K12(-1,2) K13(-0.5,2) K15(0.5,2) K16(1,2) K19(2.5,2) K20(3,2) K21(3.5,2) K22(4,2) K23(4.5,2) K24(5,2) K25(5.5,2) K26(6,2) K27(6.5,2) L1(-6.5,1.5) L2(-6,1.5) L9(-2.5,1.5) L10(-2,1.5) L11(-1.5,1.5) L12(-1,1.5) L13(-0.5,1.5) L15(0.5,1.5) L16(1,1.5) L17(1.5,1.5) L18(2,1.5) L19(2.5,1.5) L26(6,1.5) L27(6.5,1.5) M1(-6.5,1) M2(-6,1) M9(-2.5,1) M12(-1,1) M13(-0.5,1) M14(0,1) M15(0.5,1) M16(1,1) M19(2.5,1) M26(6,1) M27(6.5,1) N1(-6.5,0.5) N2(-6,0.5) N3(-5.5,0.5) N4(-5,0.5) N5(-4.5,0.5) N6(-4,0.5) N7(-3.5,0.5) N8(-3,0.5) N9(-2.5,0.5) N10(-2,0.5) N11(-1.5,0.5) N12(-1,0.5) N13(-0.5,0.5) N15(0.5,0.5) N16(1,0.5) N17(1.5,0.5) N18(2,0.5) N19(2.5,0.5) N20(3,0.5) N21(3.5,0.5) N22(4,0.5) N23(4.5,0.5) N24(5,0.5) N25(5.5,0.5) N26(6,0.5) N27(6.5,0.5) P1(-6.5,0) P2(-6,0) P3(-5.5,0) P5(-4.5,0) P7(-3.5,0) P9(-2.5,0) P12(-1,0) P13(-0.5,0) P15(0.5,0) P16(1,0) P19(2.5,0) P21(3.5,0) P23(4.5,0) P25(5.5,0) P26(6,0) P27(6.5,0) R1(-6.5,-0.5) R2(-6,-0.5) R3(-5.5,-0.5) R4(-5,-0.5) R5(-4.5,-0.5) R6(-4,-0.5) R7(-3.5,-0.5) R8(-3,-0.5) R9(-2.5,-0.5) R10(-2,-0.5) R11(-1.5,-0.5) R12(-1,-0.5) R13(-0.5,-0.5) R15(0.5,-0.5) R16(1,-0.5) R17(1.5,-0.5) R18(2,-0.5) R19(2.5,-0.5) R20(3,-0.5) R21(3.5,-0.5) R22(4,-0.5) R23(4.5,-0.5) R24(5,-0.5) R25(5.5,-0.5) R26(6,-0.5) R27(6.5,-0.5) T1(-6.5,-1) T2(-6,-1) T9(-2.5,-1) T12(-1,-1) T13(-0.5,-1) T14(0,-1) T15(0.5,-1) T16(1,-1) T19(2.5,-1) T26(6,-1) T27(6.5,-1) U1(-6.5,-1.5) U2(-6,-1.5) U9(-2.5,-1.5) U10(-2,-1.5) U11(-1.5,-1.5) U12(-1,-1.5) U13(-0.5,-1.5) U15(0.5,-1.5) U16(1,-1.5) U17(1.5,-1.5) U18(2,-1.5) U19(2.5,-1.5) U26(6,-1.5) U27(6.5,-1.5) V1(-6.5,-2) V2(-6,-2) V3(-5.5,-2) V4(-5,-2) V5(-4.5,-2) V6(-4,-2) V7(-3.5,-2) V8(-3,-2) V9(-2.5,-2) V12(-1,-2) V13(-0.5,-2) V15(0.5,-2) V16(1,-2) V19(2.5,-2) V20(3,-2) V21(3.5,-2) V22(4,-2) V23(4.5,-2) V24(5,-2) V25(5.5,-2) V26(6,-2) V27(6.5,-2) W1(-6.5,-2.5) W2(-6,-2.5) W3(-5.5,-2.5) W4(-5,-2.5) W5(-4.5,-2.5) W6(-4,-2.5) W7(-3.5,-2.5) W10(-2,-2.5) W11(-1.5,-2.5) W12(-1,-2.5) W13(-0.5,-2.5) W14(0,-2.5) W15(0.5,-2.5) W16(1,-2.5) W17(1.5,-2.5) W18(2,-2.5) W21(3.5,-2.5) W22(4,-2.5) W23(4.5,-2.5) W24(5,-2.5) W25(5.5,-2.5) W26(6,-2.5) W27(6.5,-2.5) Y1(-6.5,-3) Y2(-6,-3) Y10(-2,-3) Y13(-0.5,-3) Y15(0.5,-3) Y18(2,-3) Y26(6,-3) Y27(6.5,-3)
CC0603
  rect 0.991x0.813 smd: 1(-0.686,0) 2(0.686,0)
CON20_0P4_6P8X3P1_SM
  rect 0.203x0.711 smd: 1(-1.8,-1.54) 2(-1.8,1.54) 3(-1.4,-1.54) 4(-1.4,1.54) 5(-1,-1.54) 6(-1,1.54) 7(-0.6,-1.54) 8(-0.6,1.54) 9(-0.2,-1.54) 10(-0.2,1.54) 11(0.2,-1.54) 12(0.2,1.54) 13(0.6,-1.54) 14(0.6,1.54) 15(1,-1.54) 16(1,1.54) 17(1.4,-1.54) 18(1.4,1.54) 19(1.8,-1.54) 20(1.8,1.54)
CON100_0P4_21P7X2P05_SM
  rect 0.356x0.686 smd: (-10.275,-1.368) (-10.275,1.368) (10.275,-1.368) (10.275,1.368)
  rect 0.203x0.686 smd: 1(-9.8,1.368) 2(-9.8,-1.368) 3(-9.4,1.368) 4(-9.4,-1.368) 5(-9,1.368) 6(-9,-1.368) 7(-8.6,1.368) 8(-8.6,-1.368) 9(-8.2,1.368) 10(-8.2,-1.368) 11(-7.8,1.368) 12(-7.8,-1.368) 13(-7.4,1.368) 14(-7.4,-1.368) 15(-7,1.368) 16(-7,-1.368) 17(-6.6,1.368) 18(-6.6,-1.368) 19(-6.2,1.368) 20(-6.2,-1.368) 21(-5.8,1.368) 22(-5.8,-1.368) 23(-5.4,1.368) 24(-5.4,-1.368) 25(-5,1.368) 26(-5,-1.368) 27(-4.6,1.368) 28(-4.6,-1.368) 29(-4.2,1.368) 30(-4.2,-1.368) 31(-3.8,1.368) 32(-3.8,-1.368) 33(-3.4,1.368) 34(-3.4,-1.368) 35(-3,1.368) 36(-3,-1.368) 37(-2.6,1.368) 38(-2.6,-1.368) 39(-2.2,1.368) 40(-2.2,-1.368) 41(-1.8,1.368) 42(-1.8,-1.368) 43(-1.4,1.368) 44(-1.4,-1.368) 45(-1,1.368) 46(-1,-1.368) 47(-0.6,1.368) 48(-0.6,-1.368) 49(-0.2,1.368) 50(-0.2,-1.368) 51(0.2,1.368) 52(0.2,-1.368) 53(0.6,1.368) 54(0.6,-1.368) 55(1,1.368) 56(1,-1.368) 57(1.4,1.368) 58(1.4,-1.368) 59(1.8,1.368) 60(1.8,-1.368) 61(2.2,1.368) 62(2.2,-1.368) 63(2.6,1.368) 64(2.6,-1.368) 65(3,1.368) 66(3,-1.368) 67(3.4,1.368) 68(3.4,-1.368) 69(3.8,1.368) 70(3.8,-1.368) 71(4.2,1.368) 72(4.2,-1.368) 73(4.6,1.368) 74(4.6,-1.368) 75(5,1.368) 76(5,-1.368) 77(5.4,1.368) 78(5.4,-1.368) 79(5.8,1.368) 80(5.8,-1.368) 81(6.2,1.368) 82(6.2,-1.368) 83(6.6,1.368) 84(6.6,-1.368) 85(7,1.368) 86(7,-1.368) 87(7.4,1.368) 88(7.4,-1.368) 89(7.8,1.368) 90(7.8,-1.368) 91(8.2,1.368) 92(8.2,-1.368) 93(8.6,1.368) 94(8.6,-1.368) 95(9,1.368) 96(9,-1.368) 97(9.4,1.368) 98(9.4,-1.368) 99(9.8,1.368) 100(9.8,-1.368)
CON100_0P4_22P8X3P1_SM
  rect 0.203x0.711 smd: 1(-9.8,-1.54) 2(-9.8,1.54) 3(-9.4,-1.54) 4(-9.4,1.54) 5(-9,-1.54) 6(-9,1.54) 7(-8.6,-1.54) 8(-8.6,1.54) 9(-8.2,-1.54) 10(-8.2,1.54) 11(-7.8,-1.54) 12(-7.8,1.54) 13(-7.4,-1.54) 14(-7.4,1.54) 15(-7,-1.54) 16(-7,1.54) 17(-6.6,-1.54) 18(-6.6,1.54) 19(-6.2,-1.54) 20(-6.2,1.54) 21(-5.8,-1.54) 22(-5.8,1.54) 23(-5.4,-1.54) 24(-5.4,1.54) 25(-5,-1.54) 26(-5,1.54) 27(-4.6,-1.54) 28(-4.6,1.54) 29(-4.2,-1.54) 30(-4.2,1.54) 31(-3.8,-1.54) 32(-3.8,1.54) 33(-3.4,-1.54) 34(-3.4,1.54) 35(-3,-1.54) 36(-3,1.54) 37(-2.6,-1.54) 38(-2.6,1.54) 39(-2.2,-1.54) 40(-2.2,1.54) 41(-1.8,-1.54) 42(-1.8,1.54) 43(-1.4,-1.54) 44(-1.4,1.54) 45(-1,-1.54) 46(-1,1.54) 47(-0.6,-1.54) 48(-0.6,1.54) 49(-0.2,-1.54) 50(-0.2,1.54) 51(0.2,-1.54) 52(0.2,1.54) 53(0.6,-1.54) 54(0.6,1.54) 55(1,-1.54) 56(1,1.54) 57(1.4,-1.54) 58(1.4,1.54) 59(1.8,-1.54) 60(1.8,1.54) 61(2.2,-1.54) 62(2.2,1.54) 63(2.6,-1.54) 64(2.6,1.54) 65(3,-1.54) 66(3,1.54) 67(3.4,-1.54) 68(3.4,1.54) 69(3.8,-1.54) 70(3.8,1.54) 71(4.2,-1.54) 72(4.2,1.54) 73(4.6,-1.54) 74(4.6,1.54) 75(5,-1.54) 76(5,1.54) 77(5.4,-1.54) 78(5.4,1.54) 79(5.8,-1.54) 80(5.8,1.54) 81(6.2,-1.54) 82(6.2,1.54) 83(6.6,-1.54) 84(6.6,1.54) 85(7,-1.54) 86(7,1.54) 87(7.4,-1.54) 88(7.4,1.54) 89(7.8,-1.54) 90(7.8,1.54) 91(8.2,-1.54) 92(8.2,1.54) 93(8.6,-1.54) 94(8.6,1.54) 95(9,-1.54) 96(9,1.54) 97(9.4,-1.54) 98(9.4,1.54) 99(9.8,-1.54) 100(9.8,1.54)
CON_3_UFL_R_SMT
  rect 1.016x1.067 smd: 1(0,1.524)
  rect 1.067x2.21 smd: 2(-1.476,0) 3(1.476,0)
DFN8_1P27_6X5MM_3P1
  rect 1.016x0.61 smd: 1(-2.85,1.905) 2(-2.85,0.635) 3(-2.85,-0.635) 4(-2.85,-1.905) 5(2.85,-1.905) 6(2.85,-0.635) 7(2.85,0.635) 8(2.85,1.905)
  rect 3.099x3.099 smd: 9(0,0)
FBGA153_0P5_11P5X13
  round 0.254 smd: A1(-3.25,3.25) A2(-2.75,3.25) A3(-2.25,3.25) A4(-1.75,3.25) A5(-1.25,3.25) A6(-0.75,3.25) A7(-0.25,3.25) A8(0.25,3.25) A9(0.75,3.25) A10(1.25,3.25) A11(1.75,3.25) A12(2.25,3.25) A13(2.75,3.25) A14(3.25,3.25) B1(-3.25,2.75) B2(-2.75,2.75) B3(-2.25,2.75) B4(-1.75,2.75) B5(-1.25,2.75) B6(-0.75,2.75) B7(-0.25,2.75) B8(0.25,2.75) B9(0.75,2.75) B10(1.25,2.75) B11(1.75,2.75) B12(2.25,2.75) B13(2.75,2.75) B14(3.25,2.75) C1(-3.25,2.25) C2(-2.75,2.25) C3(-2.25,2.25) C4(-1.75,2.25) C5(-1.25,2.25) C6(-0.75,2.25) C7(-0.25,2.25) C8(0.25,2.25) C9(0.75,2.25) C10(1.25,2.25) C11(1.75,2.25) C12(2.25,2.25) C13(2.75,2.25) C14(3.25,2.25) D1(-3.25,1.75) D2(-2.75,1.75) D3(-2.25,1.75) D4(-1.75,1.75) D12(2.25,1.75) D13(2.75,1.75) D14(3.25,1.75) E1(-3.25,1.25) E2(-2.75,1.25) E3(-2.25,1.25) E5(-1.25,1.25) E6(-0.75,1.25) E7(-0.25,1.25) E8(0.25,1.25) E9(0.75,1.25) E10(1.25,1.25) E12(2.25,1.25) E13(2.75,1.25) E14(3.25,1.25) F1(-3.25,0.75) F2(-2.75,0.75) F3(-2.25,0.75) F5(-1.25,0.75) F10(1.25,0.75) F12(2.25,0.75) F13(2.75,0.75) F14(3.25,0.75) G1(-3.25,0.25) G2(-2.75,0.25) G3(-2.25,0.25) G5(-1.25,0.25) G10(1.25,0.25) G12(2.25,0.25) G13(2.75,0.25) G14(3.25,0.25) H1(-3.25,-0.25) H2(-2.75,-0.25) H3(-2.25,-0.25) H5(-1.25,-0.25) H10(1.25,-0.25) H12(2.25,-0.25) H13(2.75,-0.25) H14(3.25,-0.25) J1(-3.25,-0.75) J2(-2.75,-0.75) J3(-2.25,-0.75) J5(-1.25,-0.75) J10(1.25,-0.75) J12(2.25,-0.75) J13(2.75,-0.75) J14(3.25,-0.75) K1(-3.25,-1.25) K2(-2.75,-1.25) K3(-2.25,-1.25) K5(-1.25,-1.25) K6(-0.75,-1.25) K7(-0.25,-1.25) K8(0.25,-1.25) K9(0.75,-1.25) K10(1.25,-1.25) K12(2.25,-1.25) K13(2.75,-1.25) K14(3.25,-1.25) L1(-3.25,-1.75) L2(-2.75,-1.75) L3(-2.25,-1.75) L12(2.25,-1.75) L13(2.75,-1.75) L14(3.25,-1.75) M1(-3.25,-2.25) M2(-2.75,-2.25) M3(-2.25,-2.25) M4(-1.75,-2.25) M5(-1.25,-2.25) M6(-0.75,-2.25) M7(-0.25,-2.25) M8(0.25,-2.25) M9(0.75,-2.25) M10(1.25,-2.25) M11(1.75,-2.25) M12(2.25,-2.25) M13(2.75,-2.25) M14(3.25,-2.25) N1(-3.25,-2.75) N2(-2.75,-2.75) N3(-2.25,-2.75) N4(-1.75,-2.75) N5(-1.25,-2.75) N6(-0.75,-2.75) N7(-0.25,-2.75) N8(0.25,-2.75) N9(0.75,-2.75) N10(1.25,-2.75) N11(1.75,-2.75) N12(2.25,-2.75) N13(2.75,-2.75) N14(3.25,-2.75) P1(-3.25,-3.25) P2(-2.75,-3.25) P3(-2.25,-3.25) P4(-1.75,-3.25) P5(-1.25,-3.25) P6(-0.75,-3.25) P7(-0.25,-3.25) P8(0.25,-3.25) P9(0.75,-3.25) P10(1.25,-3.25) P11(1.75,-3.25) P12(2.25,-3.25) P13(2.75,-3.25) P14(3.25,-3.25)
GNDPOINT256
  round 5.08 hole 2.769: 1(0,0)
HDR_1X2
  rect 1.524x1.524 hole 1.016: 1(0,0)
  round 1.524 hole 1.016: 2(0,-2.54)
HVQFN56_0P4_7X7_EP4P7MM
  rect 0.889x0.203 smd: 1(-3.45,2.6) 2(-3.45,2.2) 3(-3.45,1.8) 4(-3.45,1.4) 5(-3.45,1) 6(-3.45,0.6) 7(-3.45,0.2) 8(-3.45,-0.2) 9(-3.45,-0.6) 10(-3.45,-1) 11(-3.45,-1.4) 12(-3.45,-1.8) 13(-3.45,-2.2) 14(-3.45,-2.6) 29(3.45,-2.6) 30(3.45,-2.2) 31(3.45,-1.8) 32(3.45,-1.4) 33(3.45,-1) 34(3.45,-0.6) 35(3.45,-0.2) 36(3.45,0.2) 37(3.45,0.6) 38(3.45,1) 39(3.45,1.4) 40(3.45,1.8) 41(3.45,2.2) 42(3.45,2.6)
  rect 0.203x0.889 smd: 15(-2.6,-3.45) 16(-2.2,-3.45) 17(-1.8,-3.45) 18(-1.4,-3.45) 19(-1,-3.45) 20(-0.6,-3.45) 21(-0.2,-3.45) 22(0.2,-3.45) 23(0.6,-3.45) 24(1,-3.45) 25(1.4,-3.45) 26(1.8,-3.45) 27(2.2,-3.45) 28(2.6,-3.45) 43(2.6,3.45) 44(2.2,3.45) 45(1.8,3.45) 46(1.4,3.45) 47(1,3.45) 48(0.6,3.45) 49(0.2,3.45) 50(-0.2,3.45) 51(-0.6,3.45) 52(-1,3.45) 53(-1.4,3.45) 54(-1.8,3.45) 55(-2.2,3.45) 56(-2.6,3.45)
  rect 4.699x4.699 smd: 57(0,0)
IND_0603A
  rect 1.016x1.016 smd: 1(-0.69,0) 2(0.69,0)
IND_2016A
  rect 0.864x1.803 smd: 1(-0.835,0) 2(0.835,0)
IND_SPH2520
  rect 1.219x2.007 smd: 1(-1.01,0) 2(1.01,0)
LED_0603
  rect 0.838x0.787 smd: A(-0.775,0) C(0.775,0)
MODULE_WIFI_0P9_12X12_47PIN_A
  rect 1.321x0.508 smd: 1(-5.69,4.5) 2(-5.69,3.6) 3(-5.69,2.7) 4(-5.69,1.8) 5(-5.69,0.9) 6(-5.69,0) 7(-5.69,-0.9) 8(-5.69,-1.8) 9(-5.69,-2.7) 10(-5.69,-3.6) 11(-5.69,-4.5) 23(5.69,-4.5) 24(5.69,-3.6) 25(5.69,-2.7) 26(5.69,-1.8) 27(5.69,-0.9) 28(5.69,0) 29(5.69,0.9) 30(5.69,1.8) 31(5.69,2.7) 32(5.69,3.6) 33(5.69,4.5)
  rect 0.508x1.321 smd: 12(-4.5,-5.69) 13(-3.6,-5.69) 14(-2.7,-5.69) 15(-1.8,-5.69) 16(-0.9,-5.69) 17(0,-5.69) 18(0.9,-5.69) 19(1.8,-5.69) 20(2.7,-5.69) 21(3.6,-5.69) 22(4.5,-5.69) 34(4.5,5.69) 35(3.6,5.69) 36(2.7,5.69) 37(1.8,5.69) 38(0.9,5.69) 39(0,5.69) 40(-0.9,5.69) 41(-1.8,5.69) 42(-2.7,5.69) 43(-3.6,5.69) 44(-4.5,5.69)
  round 0.61 smd: 45(-2.7,3.6) 46(-0.9,3.6) 47(0.9,3.6)
SC70_3
  rect 0.711x0.889 smd: 1(-0.648,-0.952) 2(0.648,-0.952) 3(0,0.952)
TESTPOINT_35MIL
  round 0.889 smd: 1(0,0)
TPAD_015
  round 0.381 smd: 1(0,0)
TPAD_020
  round 0.508 smd: 1(0,0)
TPAD_050
  round 1.27 smd: 1(0,0)
unnamed#2
  round 1.016 smd: (0,0)
unnamed#3
  round 1.626 hole 1.626 unplated: (-8.362,8.362) (-8.362,-8.362) (8.362,8.362) (8.362,-8.362)
  round 0.889 hole 0.889 unplated: (-8.362,-3.282) (8.362,5.822)
WLCSP4_0P4_0P8X0P8_SMDP
  round 0.254 smd: A1(-0.2,0.2) A2(0.2,0.2) B1(-0.2,-0.2) B2(0.2,-0.2)
XTAL2-3P2X1P5-SM
  rect 1.092x1.905 smd: 1(-1.25,0) 2(1.25,0)
XTLOSC4_3P2X2P5MM_SM
  rect 1.397x1.194 smd: 1(-1.1,-0.8) 2(1.1,-0.8) 3(1.1,0.8) 4(-1.1,0.8)

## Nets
GND: BH1.1 BH2.1 BH3.1 C1.2 C2.2 C3.2 C5.2 C6.2 C8.2 C9.2 C13.2 C15.2 C16.2 C17.2 C20.2 C21.2 C23.2 C30.2 C33.2 C35.2 C36.2 C48.2 C54.2 C55.2 C61.2 C65.2 C74.2 C78.2 C88.2 C89.2 C90.2 C91.2 C92.2 C93.2 C94.2 C95.2 C99.2 C100.2 C101.2 C104.2 C105.2 C106.2 C108.2 C109.2 C110.2 C111.2 C112.2 C113.2 C114.2 C115.2 C117.2 C118.2 C119.2 C121.2 C122.2 C123.2 C124.2 C127.2 C128.2 C129.2 C130.2 C131.2 C132.2 C133.2 C136.2 C137.2 C138.2 C139.2 C146.2 C148.2 C234.1 C235.2 C241.2 C244.2 C245.2 C247.2 C248.2 C251.2 C253.2 C254.2 C255.2 C256.2 C260.2 C264.2 C265.2 C266.2 C267.2 C268.2 C272.2 C273.1 C274.1 C275.2 C276.2 C279.2 C281.2 C283.2 C285.2 C287.2 C295.2 C298.2 C299.2 C301.2 C302.2 C311.2 C317.2 C318.2 C333.2 C337.2 C351.2 C363.2 C365.2 C370.2 C371.2 C372.2 C373.2 C374.2 C375.2 C376.2 C378.2 C379.2 C380.2 C381.2 C382.2 C384.2 C391.2 C392.2 C393.2 C400.2 C401.1 C402.1 C403.2 C404.2 C453.2 C454.2 C456.2 C457.2 J1.2 J1.3(GND2) J4.1 J4.7 J4.8 J4.13 J4.19 J4.20 J4.25 J4.31 J4.32 J4.37 J4.43 J4.44 J4.49 J4.55 J4.61 J4.67 J4.68 J4.73 J4.79 J4.80 J4.87 J4.92 J4.97 J5.9 J5.10 J5.11 J5.12 J5.13 J5.14 J5.15 J5.16 J5.17 J5.18 J5.19 J5.20 J5.47 J5.48 J5.60 J5.61 J5.72 J5.75 J5.84 J5.89 J6.2 J7.3 J7.6 J7.7 J7.16 J7.17 Q1.2(SOURCE) R4.1 R7.1 R18.2 R23.2 R29.2 R103.2 R121.1 R158.1 R215.2 TP44.1(PIN1) TP45.1(PIN1) TP46.1(PIN1) TP47.1(PIN1) U1.A1 U1.A27 U1.AA7 U1.AA9 U1.AA10 U1.AA13 U1.AA15 U1.AA18 U1.AA19 U1.AA21 U1.AB3 U1.AB25 U1.AC3 U1.AC25 U1.AE2 U1.AE5 U1.AE6 U1.AE9 U1.AE10 U1.AE13 U1.AE14 U1.AE15 U1.AE18 U1.AE19 U1.AE22 U1.AE23 U1.AF3 U1.AG1 U1.AG27 U1.B3 U1.B26 U1.C2 U1.C5 U1.C6 U1.C9 U1.C10 U1.C13 U1.C14 U1.C15 U1.C18 U1.C19 U1.C22 U1.C23 U1.E3 U1.E25 U1.F3 U1.F25 U1.G7 U1.G9 U1.G10 U1.G13 U1.G15 U1.G18 U1.G19 U1.G21 U1.H2 U1.H18 U1.J3 U1.J7 U1.J21 U1.J25 U1.K3 U1.K7 U1.K20 U1.K21 U1.K25 U1.L12 U1.L16 U1.M12 U1.M16 U1.N3 U1.N7 U1.N12 U1.N16 U1.N21 U1.N25 U1.P3 U1.P13 U1.P15 U1.P21 U1.P25 U1.R3 U1.R7 U1.R12 U1.R16 U1.R20 U1.R21 U1.R25 U1.T12 U1.T16 U1.U12 U1.U16 U1.V3 U1.V7 U1.V21 U1.V25 U1.W3(VSS99) U1.W7 U1.W21 U1.W25 U1.Y2 U1.Y13 U1.Y18 U2.A3 U2.A10 U2.AB3 U2.AB5 U2.AB8 U2.AB10 U2.C1 U2.C5 U2.C8 U2.C12 U2.D2 U2.D4 U2.D9(VSS9) U2.D11 U2.E1 U2.E5 U2.E8 U2.E12 U2.G1 U2.G3 U2.G5 U2.G8 U2.G10 U2.G12 U2.J1 U2.J3 U2.J10 U2.J12 U2.K2 U2.K4 U2.K9 U2.K11 U2.N2 U2.N4 U2.N9 U2.N11 U2.P1 U2.P3 U2.P10 U2.P12 U2.T1 U2.T3 U2.T5 U2.T8 U2.T10 U2.T12 U2.V1 U2.V5 U2.V8 U2.V12 U2.W2 U2.W4 U2.W9 U2.W11 U2.Y1 U2.Y5 U2.Y8 U2.Y12 U4.A6 U4.C4 U4.E7 U4.G5 U4.H10 U4.J5 U4.K8 U4.N2 U4.N5 U4.P4 U4.P6 U5.4 U5.9 U7.B2 U8.5 U8.43 U8.57 U9.1 U9.3 U9.20 U9.31 U9.33 U9.36 Y1.2 Y1.4
VDD_ARM_0V9: C33.1 C35.1 C36.1 C248.1 C251.1 C253.1 C275.1 C285.1 L5.2 R191.2 R192.1 TP22.1(TP) U1.R13 U1.R15 U1.T13 U1.T14 U1.T15 U1.U13 U1.U15 U1.V13 U1.V15 U1.V16 U1.W13 U1.W14 U1.W15 U1.W16
VDD_PHY_1V2: C244.1 C351.1 TP31.1(TP) U1.J15 U8.1
VDD_SNVS_0V8: C9.1 C337.1 R113.1 TP29.1(TP) U1.K22 U8.2
VDD_SOC&DRAM&PU_0V9: C1.1 C15.1 C16.1 C20.1 C48.1 C54.1 C55.1 C61.1 C65.1 C74.1 C78.1 C234.2 C235.1 C247.1 C254.1 C255.1 C256.1 C283.1 C287.1 L6.2 R193.1 R194.2 TP23.1(TP) U1.J10 U1.J14 U1.J17 U1.K15 U1.K16 U1.L10 U1.L15 U1.L17 U1.L18 U1.M15 U1.N10 U1.N13 U1.N15 U1.N17 U1.N18 U1.P9 U1.P12 U1.P16 U1.R10 U1.R11 U1.R17 U1.R18 U1.U10 U1.U11 U1.U17 U1.U18 U1.V12 U1.W10 U1.W11
VDDA_1V8: C99.1 C100.1 C101.1 C104.1 C265.1 C267.1 C363.1 C400.1 TP32.1(TP) U1.AA14 U1.H13 U1.H15 U1.N19 U1.N20 U1.P5 U1.P19 U1.R19 U1.Y15 U8.54
VIN_LDO_CAP: C122.1 L1.2 U9.23
VINT: C274.2 U8.4
32K_CLKIN: R115.2 U9.24
ANT_IN0: C455.1 C456.1 U9.2
BOOT_MODE0: J4.98 R47.1 U1.G26
BOOT_MODE1: J4.100 R79.1 U1.G27
BOOT_MODE2: J4.60 R78.1 U1.C27
BOOT_MODE3: J4.56 R77.1 U1.D26
BT_CTS_RES: R205.1 U9.44
BT_RTS_RES: R208.1 U9.41
BT_RXD_RES: R206.1 U9.43
BT_TXD_RES: R207.1 U9.42
BT_WAKE_DEV: U1.U26 U9.6
BT_WAKE_HOST: U1.W27 U9.7
CLK_32K_OUT: R100.1 U8.7
CLKIN1: J4.94 TP20.1(PIN1) U1.H27
CLKIN2: J4.96 TP21.1(PIN1) U1.J27
CLKOUT1: J4.64 U1.H26
CLKOUT2: J4.66 U1.J26
CSI_CKN: J4.45 U1.A16
CSI_CKP: J4.47 U1.B16
CSI_DN0: J4.33 U1.A14
CSI_DN1: J4.39 U1.A15
CSI_DN2: J4.51 U1.A17
CSI_DN3: J4.57 U1.A18
CSI_DP0: J4.35 U1.B14
CSI_DP1: J4.41 U1.B15
CSI_DP2: J4.53 U1.B17
CSI_DP3: J4.59 U1.B18
DRAM_CA0_A: U1.J6 U2.H2
DRAM_CA1_A: U1.K6 U2.J2
DRAM_CA2_A: U1.E4 U2.H9
DRAM_CA3_A: U1.D5 U2.H10
DRAM_CA4_A: U1.N4 U2.H11
DRAM_CA5_A: U1.N5 U2.J11
DRAM_CK_C_A: R8.2 U1.L1 U2.J9
DRAM_CK_T_A: R8.1 U1.L2 U2.J8
DRAM_CKE0_A: R121.2 U1.F4 U2.J4
DRAM_CKE1_A: R158.2 U1.F5 U2.J5
DRAM_DMI0: U1.A4 U2.C3
DRAM_DMI1: U1.F1 U2.C10
DRAM_DQ00: U1.A5 U2.B2
DRAM_DQ01: U1.B5 U2.C2
DRAM_DQ02: U1.D2 U2.E2
DRAM_DQ03: U1.D1 U2.F2
DRAM_DQ04: U1.C1 U2.F4
DRAM_DQ05: U1.B1 U2.E4
DRAM_DQ06: U1.A3 U2.C4
DRAM_DQ07: U1.B4 U2.B4
DRAM_DQ08: U1.F2 U2.B11
DRAM_DQ09: U1.G2 U2.C11
DRAM_DQ10: U1.J1 U2.E9
DRAM_DQ11: U1.J2 U2.E11
DRAM_DQ12: U1.K2 U2.F11
DRAM_DQ13: U1.K1 U2.F9
DRAM_DQ14: U1.E1 U2.B9
DRAM_DQ15: U1.E2 U2.C9
DRAM_NCS0_A: U1.K4 U2.H4
DRAM_NCS1_A: U1.J4 U2.H3
DRAM_NRESET: R4.2 R204.2 U1.R1 U2.T11
DRAM_SDQS0_C: U1.B2 U2.E3
DRAM_SDQS0_T: U1.A2 U2.D3
DRAM_SDQS1_C: U1.H1 U2.E10
DRAM_SDQS1_T: U1.G1 U2.D10
DRAM_ZQ0: R5.2 U2.A5
DRAM_ZQ1: R157.2 U2.A8
DSI_CKN: J4.15 U1.A11
DSI_CKP: J4.17 U1.B11
DSI_DN0: J4.3 U1.A9
DSI_DN1: J4.9 U1.A10
DSI_DN2: J4.21 U1.A12
DSI_DN3: J4.27 U1.A13
DSI_DP0: J4.5 U1.B9
DSI_DP1: J4.11 U1.B10
DSI_DP2: J4.23 U1.B12
DSI_DP3: J4.29 U1.B13
ECSPI2_MISO: J4.16 U1.A8
ECSPI2_MOSI: J4.18 U1.B8
ECSPI2_SCLK: J4.14 U1.E6
ECSPI2_SS0: J4.12 U1.A6
EMMC_VDDIM: C136.1 C137.1 U4.C2
ENET_MDC: J7.18 U1.AC27
ENET_MDIO: J7.20 U1.AB27
ENET_RD0: J7.8 U1.AE27
ENET_RD1: J7.10 U1.AD27
ENET_RD2: J7.12 U1.AD26
ENET_RD3: J7.14 U1.AC26
ENET_RX_CTL: J7.2 U1.AF27
ENET_RXC: J7.4 U1.AE26
ENET_TD0: J7.9 U1.AG26
ENET_TD1: J7.11 U1.AF26
ENET_TD2: J7.13 U1.AG25
ENET_TD3: J7.15 U1.AF25
ENET_TX_CTL: J7.1 U1.AF24
ENET_TXC: J7.5 U1.AG24
GPIO1_IO01: J5.64 U1.AF14
GPIO1_IO05: J5.62 U1.AF12
GPIO1_IO06: J5.58 U1.AG11
GPIO1_IO07: J5.56 U1.AF11
GPIO1_IO08: J5.54 U1.AG10
GPIO1_IO09: J5.52 U1.AF10
GPIO1_IO10: J5.50 U1.AD10
GPIO1_IO11: J5.46 U1.AC10
GPIO1_IO12: J5.44 U1.AB10
GPIO1_IO13: J5.42 U1.AD9
GPIO1_IO14: J5.40 U1.AC9
GPIO1_IO15: J5.38 U1.AB9
I2C1_SCL: R10.2 R48.1 U1.E9
I2C1_SDA: R11.2 R54.1 U1.F9
I2C2_SCL: J4.22 R12.2 U1.D10
I2C2_SDA: J4.24 R13.2 U1.D9
I2C3_SCL: J4.26 R14.2 U1.E10
I2C3_SDA: J4.28 R15.2 U1.F10
I2C4_SCL: J4.30 R16.2 U1.D13
I2C4_SDA: J4.34 R17.2 U1.E13
JTAG_MOD: R23.1 U1.D27
JTAG_TCK: J4.62 R18.1 TP4.1(PIN1) U1.F26
JTAG_TDI: J4.54 TP2.1(PIN1) U1.E27
JTAG_TDO: J4.52 TP5.1(PIN1) U1.E26
JTAG_TMS: J4.58 R27.2 TP3.1(PIN1)
JTAG_TMS_R: R27.1 U1.F27
LX1: L6.1 U8.36 U8.37
LX2: L5.1 U8.45 U8.46
LX4: L11.1 U8.19 U8.20
LX5: L13.1 U8.15
LX6: L15.1 U8.50 U8.51
M.2_32K_OUT: J5.37 R116.2
NVCC_1V8: C3.1 C5.1 C21.1 C23.1 C105.1 C106.1 C108.1 C109.1 C130.1 C131.1 C132.1 C133.1 C138.1 C139.1 C146.1 C241.1 C266.1 C317.1 C370.1 C371.1 C372.1 C384.1 C404.1 J5.22 J5.24 J5.26 J5.28 J5.30 J5.32 J5.34 J5.36 L13.2 R10.1 R11.1 R12.1 R13.1 R14.1 R15.1 R16.1 R17.1 R37.1 R47.2 R61.2 R77.2 R78.2 R79.2 R106.1 R117.1 R118.1 R196.1 R197.1 TP26.1(TP) U1.AB13 U1.J11 U1.J12 U1.J13 U1.L19 U1.M19 U1.T19 U1.U19 U1.V19 U1.V20 U1.W12 U2.F1 U2.F12 U2.G4 U2.G9 U2.T4 U2.T9 U2.U1 U2.U12 U4.C6 U4.M4 U4.N4 U4.P3 U4.P5 U5.8 U7.A1 U8.14
NVCC_3V3: C6.1 C8.1 C30.1 C121.1 C127.1 C128.1 C129.1 C260.1 C264.1 C276.1 C311.1 C403.1 J5.21 J5.23 J5.25 J5.27 J5.29 J5.31 J5.33 J5.35 L11.2 R125.1 R137.1 R153.1 R200.1 R201.1 TP25.1(TP) U1.H10 U1.K19 U1.W17 U1.Y10 U4.E6 U4.F5 U4.J10 U4.K9 U8.21 U8.22 U9.9
NVCC_DRAM_1V1: C88.1 C89.1 C90.1 C91.1 C92.1 C93.1 C94.1 C95.1 C110.1 C111.1 C112.1 C113.1 C114.1 C115.1 C117.1 C118.1 C119.1 C318.1 C373.1 C374.1 C375.1 C376.1 C378.1 C379.1 C380.1 C381.1 C382.1 L15.2 R5.1 R157.1 TP27.1(TP) U1.K8 U1.K9 U1.L9 U1.M9 U1.N8 U1.N9 U1.P7 U1.R8 U1.R9 U1.T9 U1.U9 U1.V8 U1.V9 U2.A4 U2.A9 U2.AA3 U2.AA5 U2.AA8 U2.AA10 U2.AB4 U2.AB9 U2.B3 U2.B5 U2.B8 U2.B10 U2.D1 U2.D5 U2.D8 U2.D12 U2.F3 U2.F5 U2.F8 U2.F10 U2.G2 U2.H1 U2.H5 U2.H8 U2.H12 U2.K1 U2.K3 U2.K10 U2.K12 U2.N1 U2.N3 U2.N10 U2.N12 U2.R1 U2.R5 U2.R8 U2.R12 U2.U3 U2.U5 U2.U8 U2.U10 U2.W1 U2.W5 U2.W8 U2.W12 U8.52
NVCC_ENET: C2.1 C392.1 J7.19 U1.W22
NVCC_SD2: C17.1 C365.1 R119.1 R120.1 R133.1 TP33.1(TP) U1.V22 U8.55
NVCC_SNVS_1V8: C333.1 C391.1 R20.1 R21.1 R102.1 TP28.1(TP) U1.J22 U8.3
ONOFF: J4.46 R21.2 TP7.1(TP) U1.A25
PDM_CLK: J5.65 U1.AC15
PDM_DATA0: J5.67 U1.AD18
PDM_DATA1: J5.69 U1.AC14
PDM_DATA2: J5.71 U1.AD13
PDM_DATA3: J5.73 U1.AC13
PHY_VREF: TP58.1(PIN1) U1.P1
PMIC_NINT: R61.1 U1.AF13 U8.13
PMIC_ON_REQ: J4.48 R51.1 TP6.1(TP) U1.A24
PMIC_STBY_REQ: R52.1 TP10.1(TP) U1.E24
POR_B: J4.50 R20.2 R114.2 TP9.1(TP) U1.B24
QSPIA_DATA0: TP16.1(TP) U1.P23 U5.5
QSPIA_DATA1: U1.K24 U5.2
QSPIA_DATA2: U1.K23 U5.3(W\/DQ2)
QSPIA_DATA3: U1.N23 U5.7
QSPIA_NSS0: R37.2 U1.N24 U5.1
QSPIA_SCLK: TP17.1(TP) U1.N22 U5.6
R_SNSP1: R193.2 R194.1 U8.38
R_SNSP2: R191.1 R192.2 U8.44
REF_CLK_32K: R115.1 R116.1 U1.AG14
REG_PD_B: U1.R23 U9.12
RF_ANT0: C455.2 C457.1 J1.1
RTC_RESET_B: R102.2 R111.2 TP8.1(TP) U1.F24
SAI2_MCLK: J5.66 U1.AD19
SAI2_RXC: J5.79 U1.AB22
SAI2_RXD: R132.2 U1.AC24
SAI2_RXD_RES: R132.1 U9.25
SAI2_RXFS: J5.68 U1.AC19
SAI2_TXC: R131.2 R198.1 U1.AD22
SAI2_TXC_1P8: R196.2 R198.2 U8.27
SAI2_TXC_3P3: J5.87 R203.1
SAI2_TXC_RES: R131.1 U9.26
SAI2_TXD: R130.2 R199.1 U1.AC22
SAI2_TXD_1P8: R197.2 R199.2 U8.26
SAI2_TXD_3P3: J5.91 R202.1
SAI2_TXD_RES: R130.1 U9.27
SAI2_TXFS: R129.2 U1.AD23
SAI2_TXFS_RES: R129.1 U9.28
SAI3_MCLK: J5.41 U1.AD6
SAI3_RXC: J5.53 U1.AG7
SAI3_RXD: J5.55 U1.AF7
SAI3_RXFS: J5.51 U1.AG8
SAI3_TXC: J5.45 U1.AG6
SAI3_TXD: J5.49 U1.AF6
SAI3_TXFS: J5.43 U1.AC6
SAI5_MCLK: J5.77 U1.AD15
SAI5_RXFS: J5.70 U1.AB15
SD1_CLK: R214.1 TP66.1(PIN1) U1.V26
SD1_CLK_R: R214.2 U9.17
SD1_CMD: R213.1 TP67.1(PIN1) U1.V27
SD1_CMD_R: R213.2 U9.16
SD1_DATA0: R209.1 TP24.1(PIN1) U1.Y27
SD1_DATA0_R: R209.2 U9.18
SD1_DATA1: R210.1 U1.Y26
SD1_DATA1_R: R210.2 U9.19
SD1_DATA2: R211.1 U1.T27
SD1_DATA2_R: R211.2 U9.14
SD1_DATA3: R212.1 U1.T26
SD1_DATA3_R: R212.2 U9.15
SD1_STROBE: J4.70 U1.R24
SD2_CLK: J4.76 U1.W23
SD2_CMD: J4.78 R120.2 U1.W24
SD2_DATA0: J4.84 R119.2 U1.AB23
SD2_DATA1: J4.82 U1.AB24
SD2_DATA2: J4.72 U1.V24
SD2_DATA3: J4.74 U1.V23
SD2_NCD: J4.88 U1.AA26
SD2_NRST: J4.90 R133.2 U1.AB26
SD2_VSEL: U1.AG12 U8.29
SD2_WP: J4.86 U1.AA27
SD3_CLK: TP34.1(PIN1) U1.R26 U4.M6
SD3_CMD: R118.2 TP35.1(PIN1) U1.R27 U4.M5
SD3_DATA0: R117.2 TP36.1(PIN1) U1.M26 U4.A3
SD3_DATA1: U1.L26 U4.A4
SD3_DATA2: U1.K26 U4.A5
SD3_DATA3: U1.N26 U4.B2
SD3_DATA4: U1.N27 U4.B3
SD3_DATA5: U1.M27 U4.B4
SD3_DATA6: U1.L27 U4.B5
SD3_DATA7: U1.K27 U4.B6
SD3_STROBE: TP40.1(PIN1) U1.P27 U4.H5
SPDIF_EXT_CLK: J5.63 U1.AF8
SPDIF_RX: J5.59 U1.AG9
SPDIF_TX: J5.57 U1.AF9
SW_EN: R137.2 U8.12
SWOUT_3V3: C273.2 TP68.1(TP) U8.23
SYS_NRST: J5.39 R127.1
SYS_STATUS: Q1.1 U1.P26
TS_RES_EXT: R103.1 U1.J24
TS_TEST_OUT: TP19.1(PIN1) U1.J23
UART1_CTS: R205.2 U1.E18
UART1_RTS: R208.2 U1.D18
UART1_RXD: R207.2 U1.E14
UART1_TXD: R206.2 U1.F13
UART2_RXD: J4.36 U1.F15
UART2_TXD: J4.38 U1.E15
UART3_CTS: J4.10 U1.A7
UART3_RTS: J4.2 U1.B6
UART3_RXD: J4.4 U1.D6
UART3_TXD: J4.6 U1.B7
UART4_RXD: J4.40 U1.F19
UART4_TXD: J4.42 U1.F18
USB1_DN: J4.83 U1.A22
USB1_DP: J4.85 U1.B22
USB1_ID: J4.89 U1.D22
USB1_VBUS: C393.1 J4.81 R108.2
VSYS_5V: C13.1 C272.1 C279.1 C281.1 C295.1 C301.1 C302.1 C401.2 C402.2 C453.1 J5.1 J5.2 J5.3 J5.4 J5.5 J5.6 J5.7 J5.8 J6.1 R195.2 TP51.1(TP) U8.16 U8.17 U8.18 U8.33 U8.34 U8.35 U8.47 U8.48 U8.49 U8.53 U8.56
WDOG_B: R55.1 TP53.1(TP) U1.AG13
WIFI_1V8: C454.1 TP13.1(PIN1) U7.A2(VOUT) U9.22
WL_WAKE_DEV: U1.U27 U9.39
WL_WAKE_HOST: U1.W26 U9.13
XIN_32K: C298.1 QZ2.2 U8.10
XOUT_32K: C299.1 QZ2.1 U8.11(XTAL_OUT)
XTALI_24M: C123.1 R26.1 TP38.1(PIN1) U1.B27 Y1.3
XTALI_32K: R100.2 TP39.1(PIN1) U1.A26
XTALO_24M: C124.1 R26.2 U1.C26 Y1.1
XTALO_32K: R113.2 U1.B25
N102271152: R7.2 U1.P2
N106370682: R108.1 U1.F22
N106370752: R29.1 U1.E19
N106740715: R114.1 U8.9
N106743010: R55.2 R106.2 U8.28
N106743238: R51.2 U8.39
N106743319: R52.2 U8.40
N106743947: R111.1 U8.6
N107005929: TP15.1(PIN1) U1.N2
N108008688: R127.2 U8.8
N108250870: C268.1 U1.D15
N109411711: R195.1 U8.30
N109413799: R48.2 U8.41
N109414410: R54.2 U8.42
N109458619: TP18.1(PIN1) U4.K5
N109477029: D1.C(CATHODE) Q1.3
N109477483: C245.1 U1.R22
N109540553: R201.2 R203.2 U8.25
N109540574: R200.2 R202.2 U8.24
N109586960: R204.1 U2.G11
N109658934: L1.1 U9.21
N109688415: C148.1 R153.2 R215.1 TP12.1(PIN1) U7.B1
N1094770141: D1.A R125.2

Pads without a net: J4 63 65 69 71 75 77 91 93 95 99; J5 74 76 78 80 81 82 83 85 86 88 90 92 93 94 95 96 97 98 99 100; U1 A19 A20 A21 A23 AA1 AA2 AB1 AB2 AB4 AB5 AB6 AB18 AB19 AC1 AC2 AC4 AC18 AD1 AD2 AD5 AE1 AF1 AF2 AF4 AF5 AF15 AF16 AF17 AF18 AF19 AF20 AF21 AF22 AF23 AG2 AG3 AG4 AG5 AG15 AG16 AG17 AG18 AG19 AG20 AG21 AG22 AG23 B19 B20 B21 B23 D19 D23 E22 F6 F23 G14 J5 J16 J18 K5 K12 K13 L11 L13 M1 M2 M13 M14 N1 N6 N11 R2 R4 R5 R6 T1 T2 U1 U2 V1 V2 V4 V5 V6 W1 W2 W4 W5 W6 W18 Y1; U2 A1 A2 A11 A12 AA1 AA2 AA4 AA9 AA11 AA12 AB1 AB2 AB11 AB12 B1 B12 K5 K8 N5 N8 P2 P4 P5 P8 P9 P11 R2 R3 R4 R9 R10 R11 T2 U2 U4 U9 U11 V2 V3 V4 V9 V10 V11 W3 W10 Y2 Y3 Y4 Y9 Y10 Y11; U4 A1 A2 A7 A8 A9 A10 A11 A12 A13 A14 B1 B7 B8 B9 B10 B11 B12 B13 B14 C1 C3 C5 C7 C8 C9 C10 C11 C12 C13 C14 D1 D2 D3 D4 D12 D13 D14 E1 E2 E3 E5 E8 E9 E10 E12 E13 E14 F1 F2 F3 F10 F12 F13 F14 G1 G2 G3 G10 G12 G13 G14 H1 H2 H3 H12 H13 H14 J1 J2 J3 J12 J13 J14 K1 K2 K3 K6 K7 K10 K12 K13 K14 L1 L2 L3 L12 L13 L14 M1 M2 M3 M7 M8 M9 M10 M11 M12 M13 M14 N1 N3 N6 N7 N8 N9 N10 N11 N12 N13 N14 P1 P2 P7 P8 P9 P10 P11 P12 P13 P14; U8 31 32; U9 4 5 8 10 11 29 30 32 34 35 37 38 40 45 46 47

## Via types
v1: diameter 0.406, hole 0.203, TOP to BOTTOM, 1013 vias
v2: diameter 0.457, hole 0.254, TOP to BOTTOM, 131 vias

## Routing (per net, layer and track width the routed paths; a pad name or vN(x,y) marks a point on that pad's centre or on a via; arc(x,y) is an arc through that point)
GND: length 257
  TOP w0.076: U1.C2 17.24,34.96 17.24,35.31 16.99,35.56 U1.A1 ; U1.AA19 25.97,25.74 v1(25.97,26.18) ; v1(41.03,32.82) 41.26,32.59 41.79,32.59 U4.N2 41.78,33.1 41.31,33.1 v1(41.03,32.82)
  TOP w0.178: U1.AE2 17.99,24.21 v1(17.99,24.28)
  TOP w0.203: U8.43 13.09,14.19 v2(13.28,14.39) ; U1.AA15 23.61,25.33 23.37,25.33 U1.AA13 ; v2(5.74,11.74) 5.75,11.74 U8.5 ; v1(27.49,29.22) 27.48,29.21 U1.P21 ; v1(29.02,34.73) 29.02,34.74 U1.B26
  TOP w0.254: U1.AG27 30.18,22.71 v1(30.41,22.49) ; U1.T16 U1.R16 ; U1.T16 U1.U16 ; U1.T16 24.94,28.21 v1(24.95,28.19) ; U4.G5 43.26,35.84 43.09,36.01 v1(43.03,36.01) ; U2.P10 9.31,27.91 v1(9.38,27.91) 9.46,27.91 U2.N11 ; U4.N5 U4.P4 v1(43.04,31.85) ; 17.99,34.15 U1.E3 U1.F3 17.99,32.81 v1(18.06,32.74) 18.09,32.71 v1(18.09,32.21) ; 17.99,34.15 17.99,34.71 v1(17.95,34.75) ; 17.99,34.15 v1(17.97,34.18) ; U2.K4 3.9,30.47 v1(3.75,30.47) U2.J3 ; U2.A10 9.1,36.03 v1(9.38,35.75) ; v1(32.65,39.45) 33.31,39.45 C123.2 ; U4.K8 45.04,34.71 v1(44.93,34.82) ; U4.H10 46.19,35.49 46.48,35.49 v1(46.49,35.5) ; v1(36.73,39.6) Y1.2 v1(36.73,37.49) ; U1.C2 17.92,34.71 v1(17.95,34.75) ; U2.G1 v1(2.12,31.79) ; U2.N2 2.26,27.91 v1(2.18,27.91) 2.11,27.91 U2.P1 ; U2.K2 v1(2.98,29.79) ; v1(5.43,26.28) U2.T5 ; U2.V1 2.11,24.66 v1(2.18,24.66) 2.26,24.66 U2.W2 v1(2.99,23.93) ; v1(17.95,34.75) 18.51,34.75 v1(18.52,34.76) 18.57,34.71 U1.C5 U1.C6 19.53,34.74 v1(20.25,34.74) 20.96,34.74 U1.C9 U1.C10 21.59,34.8 v1(22.2,34.8) 22.9,34.8 U1.C13 U1.C14 U1.C15 24.05,34.77 v1(24.74,34.77) 24.77,34.74 25.46,34.74 U1.C18 U1.C19 26.06,34.77 v1(26.73,34.77) 26.79,34.71 U1.C22 U1.C23 28.41,34.71 v1(28.45,34.75) 28.47,34.73 v1(29.02,34.73) 29.03,34.72 v1(29.03,34.16) 29.03,33.75 U1.E25 U1.F25 29.08,33.12 v1(29.08,32.46) 29.08,31.8 U1.J25 U1.K25 29.08,31.13 v1(29.08,30.48) 29.08,29.79 U1.N25 U1.P25 U1.R25 29.06,28.65 v1(29.06,27.96) 29.06,27.27 U1.V25 U1.W25 29.07,26.63 29.07,26.05 29.08,26.04 v1(29.08,25.99) 29.08,25.98 29.07,25.97 29.07,25.6 29.07,25.28 U1.AB25 U1.AC25 29.04,24.66 v1(29.04,24.03) 29.04,23.81 28.92,23.68 v1(28.5,23.68) 28.47,23.71 U1.AE23 U1.AE22 27.46,23.68 v1(26.77,23.68) 26.02,23.68 U1.AE19 U1.AE18 25.45,23.66 v1(24.75,23.66) 24.04,23.66 U1.AE15 U1.AE14 U1.AE13 22.96,23.68 22.25,23.68 v1(22.25,23.67) 22.25,23.68 21.53,23.68 U1.AE10 U1.AE9 20.96,23.67 v1(20.26,23.67) 20.23,23.65 19.55,23.65 U1.AE6 U1.AE5 v1(18.56,23.71) ; v1(17.95,34.75) 17.95,35.17 U1.B3 ; U2.G10 9.29,31.83 v1(9.38,31.83) ; v1(7.82,27.96) 7.91,27.96 U2.N9 ; U1.T12 22.05,28.21 v1(22.04,28.19) ; U1.T12 U1.R12 ; U1.T12 U1.U12 ; U1.R21 26.99,28.47 26.93,28.41 v1(26.93,27.96) 26.93,27.27 U1.V21 U1.W21 26.58,26.3 v1(26.58,26.2) 26.99,25.79 U1.AA21 ; U1.R21 U1.P21 U1.N21 26.95,29.75 v1(26.95,30.46) 26.95,31.17 U1.K21 ; U1.R21 U1.R20 ; U2.V8 v1(6.93,24.98) ; U1.G18 25.27,32.71 25.22,32.66 v1(24.76,32.66) 24.04,32.66 U1.G15 ; U1.G18 U1.H18 ; U1.G18 U1.G19 26.12,32.58 v1(26.45,32.58) ; U1.AA10 22.14,25.71 v1(22.19,25.76) 22.24,25.71 U1.AA13 U1.Y13 ; U1.P15 23.52,29.21 v1(23.5,29.19) 23.48,29.21 U1.P13 ; v1(18.09,32.21) 18.09,31.8 U1.J3 U1.K3 17.99,30.8 17.93,30.74 v1(17.93,30.69) 17.96,30.66 17.96,30.21 v1(17.92,30.17) 17.99,30.11 U1.N3 U1.P3 U1.R3 17.95,28.66 v1(17.95,28.24) v1(17.95,27.7) 17.95,27.69 17.95,27.66 17.96,27.65 17.96,27.61 17.99,27.57 U1.V3 U1.W3 17.99,26.54 v1(18.21,26.32) ; v1(18.09,32.21) U1.H2 ; U2.K9 8.12,30.18 v1(7.82,29.88) ; v1(26.45,32.58) 26.58,32.71 U1.G21 U1.J21 ; v1(26.45,32.58) 26.45,32.26 U1.J21 ; v1(2.16,35.05) 2.1,35.05 U2.C1 ; U1.G7 U1.G9 ; U1.G7 19.91,32.63 19.91,32.27 v1(19.92,32.26) 19.92,31.78 U1.J7 U1.K7 19.99,30.78 19.96,30.75 v1(19.96,30.2) 19.99,30.17 U1.N7 ; U1.G7 19.99,33.14 v1(19.93,33.21) ; U1.G9 20.99,32.43 20.74,32.17 v1(20.54,32.17) ; U1.G9 U1.G10 21.54,32.67 v1(22.25,32.67) 22.95,32.67 U1.G13 ; U2.N4 v1(3.86,27.91) 3.71,27.91 U2.P3 ; U4.E7 44.54,36.53 44.67,36.4 v1(44.67,36.25) ; U2.K11 9.46,30.51 v1(9.37,30.51) 9.37,30.51 9.31,30.51 U2.J10 ; v1(6.86,33.58) 6.88,33.55 7.26,33.55 U2.E8 ; U1.J21 U1.K21 ; U2.G3 2.98,31.73 v1(2.98,31.69) ; U2.C8 v1(7.74,34.38) 7.89,34.38 U2.D9 ; U2.T3 v1(3,26.67) ; v1(6.02,31.47) 5.35,32.13 U2.G5 ; U1.M12 U1.L12 ; U1.M12 U1.N12 ; U1.M12 v1(22.01,30.21) ; v1(2.88,36.37) 3.22,36.03 U2.A3 ; U2.W9 8.01,24.33 7.75,24.07 v1(7.75,24.05) U2.Y8 ; U1.K21 U1.K20 ; U2.V5 v1(5.43,24.98) ; U2.T8 v1(6.93,26.28) ; Y1.4 35.18,36.26 v1(35.18,35.31) 35.17,35.29 34.43,35.29 34.25,35.47 C124.2 ; U2.AB5 v1(5.43,22.38) ; C298.2 3.58,11.3 v2(3.35,11.53) ; U4.A6 44.04,38.96 44.29,39.21 44.29,39.21 v1(44.3,39.22) ; v1(6.86,32.13) 6.86,32.13 U2.G8 ; U1.N16 U1.M16 ; U1.M16 U1.L16 ; U1.M16 24.9,30.21 v1(24.95,30.26) ; C274.1 v2(3.94,12.52) ; TP44.1 v1(8.71,42.49) ; TP44.1 v1(9.65,43.43) ; TP44.1 v1(9.65,41.55) ; TP44.1 v1(10.59,42.49) ; U4.P6 44.04,32.28 44.33,31.98 v1(44.33,31.85) ; U2.P12 11.03,27.58 v1(11.08,27.63) ; v1(43.01,34.84) U4.J5 ; U2.AB3 3.11,22.66 v1(3.02,22.66) ; v1(9.34,26) 9.27,26 U2.T10 ; U2.W4 4.51,24 v1(4.52,24) 4.66,24 U2.Y5 ; U2.E1 2.11,33.76 v1(2.18,33.76) 2.26,33.76 U2.D2 2.9,34.41 v1(2.98,34.41) ; v1(9.35,22.65) 9.09,22.38 U2.AB10 ; U2.G12 11.07,32.13 v1(11.08,32.12) ; U2.Y1 v1(2.12,23.35) ; U2.E5 5.27,33.43 v1(5.41,33.58) ; v1(9.37,33.67) U2.D11 10.03,34.33 10.12,34.33 10.15,34.37 v1(10.23,34.37) 10.23,34.39 U2.C12 ; U2.AB8 v1(6.93,22.38) ; v1(11.08,30.74) 10.99,30.83 U2.J12 ; U2.C5 4.85,34.73 v1(4.53,34.42) 4.51,34.42 U2.D4 ; TP45.1 25.32,9.85 v2(25.37,9.9) ; v1(11.1,33.46) 11.08,33.43 U2.E12 ; v1(18.21,26.32) 18.11,26.21 U1.Y2 ; v1(18.21,26.32) 18.21,25.61 17.99,25.39 U1.AB3 U1.AC3 17.99,24.71 v1(17.99,24.28) 18.56,23.71 v1(18.56,23.71) ; v1(18.56,23.71) 18.45,23.6 18.26,23.6 17.99,23.33 U1.AF3 ; U1.B26 U1.A27 30.14,35.85 v1(30.14,36.14) ; U2.T1 v1(2.12,25.95) ; v1(11.07,26.28) U2.T12 ; v1(16.56,22.71) U1.AG1 ; U2.Y12 10.26,24.01 v1(10.18,24.01) 10.11,24.01 U2.W11 ; C299.2 v2(3.58,8.08) ; U4.C4 43.47,37.41 v1(43.47,37.36) ; U1.AA19 U1.AA18 25.42,25.78 24.72,25.78 v1(24.69,25.75) 24.04,25.75 U1.AA15 ; v1(25.97,26.18) 25.93,26.21 U1.Y18 ; U2.J1 v1(2.1,30.52) ; U1.W7 U1.V7 19.99,27.64 v1(19.97,27.66) 19.97,28.25 v1(19.99,28.27) U1.R7 ; U2.V12 v1(11.08,24.98)
  TOP w0.381: U9.36 v2(56.52,22.72) ; U9.31 v2(52.49,26.72) ; U9.33 v2(52.48,24.92) ; U9.20 56.52,36 v2(56.42,36.1)
  BOTTOM w0.152: J4.13 16.07,46.17 v1(15.98,46.08) ; J4.7 v1(14.87,46.04) ; J4.25 18.47,46.16 v1(18.4,46.09) ; v1(32.87,46.09) 32.87,46.09 J4.97 ; v1(26.8,46.09) 26.87,46.16 J4.67 ; J4.37 20.87,46.18 v1(20.78,46.08) ; v1(25.6,46.05) 25.67,46.11 J4.61 ; J4.87 30.87,46.26 v1(30.69,46.08) ; J4.19 17.27,46.16 v1(17.17,46.07) ; J4.73 28.07,46.14 v1(28.02,46.09) ; J4.55 v1(24.47,46.09) ; J4.49 v1(23.27,46.09) ; J4.79 29.27,46.14 v1(29.22,46.09) ; J4.43 v1(22.07,46.09) ; v1(13.81,46.04) 13.67,46.18 J4.1 ; J4.31 19.67,46.26 v1(19.51,46.1)
  BOTTOM w0.178: C95.2 21.45,31.17 21.79,30.83 C78.2
  BOTTOM w0.203: v1(36.85,9.71) 36.85,9.71 J5.75 ; J5.89 39.65,9.82 v2(39.66,9.83) ; v1(22.04,28.19) 22.28,28.19 C55.2 ; v1(22.04,28.19) 22.04,28.25 21.75,28.53 C54.2 ; v1(22.04,28.19) 22.04,28.15 C61.2 ; v1(19.99,28.27) 19.99,28.32 19.84,28.47 19.84,28.5 19.77,28.56 C93.2 ; J5.61 34.05,9.71 v1(33.91,9.85) ; C74.2 21.59,29.67 21.59,29.03 21.75,28.87 C54.2 ; v1(26.87,48.82) 26.87,48.82 J4.68 ; v1(50.35,23.32) 49.98,23.32 49.75,23.1 J7.6 ; v1(31.18,9.71) 31.25,9.64 J5.47 ; C379.2 11.18,32.02 v1(11.08,32.12) ; C95.2 21.86,31.75 C1.2 ; C54.2 21.35,28.71 21.18,28.55 C90.2 ; J7.3 v1(45.37,22.7) ; J5.60 v1(33.65,5.18) ; C5.2 24.01,33.13 24.22,32.92 C100.2 24.22,32.52 23.92,32.23 C65.2 ; J4.20 v1(17.27,48.83) ; J4.80 29.27,49.09 29.46,48.89 v1(29.46,48.74) ; C266.2 22.53,23.02 22.77,23.25 C21.2 ; v1(22.19,25.76) 22.2,25.75 C251.2 ; J5.48 31.25,5.55 31.21,5.51 31.21,5.51 31.14,5.44 31.14,5.22 v1(31.04,5.12) ; J5.84 38.45,5.24 v1(38.47,5.22) ; C78.2 22.01,30.48 v1(22.01,30.21) ; v1(22.29,48.81) 22.07,49.03 J4.44 ; J4.92 31.67,48.94 v1(31.78,48.83) ; J7.7 v1(45.37,23.5) ; J7.17 v1(45.24,25.5) ; J7.16 49.52,25.1 49.69,25.26 49.77,25.26 v1(49.77,25.27) ; v1(36.17,5.2) 36.07,5.3 36.07,5.47 36.05,5.49 J5.72
  BOTTOM w0.254: 21.26,33.55 21.49,33.32 C8.2 21.73,32.73 21.79,32.67 v1(22.25,32.67) ; C235.2 24.95,30.42 v1(24.95,30.26) ; C30.2 26.77,32.58 v1(26.45,32.58) ; C111.2 10.28,24.11 v1(10.18,24.01) ; C133.2 43.04,31.44 v1(43.04,31.85) ; C234.1 26.98,29.72 v1(27.49,29.22) 27.49,28.89 C104.2 ; C248.2 26.06,26.71 C23.2 ; v1(2.12,23.35) 2.04,23.27 C119.2 ; C382.2 6.94,26.28 v1(6.93,26.28) ; v1(26.77,23.68) 26.77,23.39 27.05,23.11 C2.2 ; v1(9.38,27.91) 9.42,27.87 C110.2 ; v1(35.18,35.31) 34.66,34.79 R18.2 ; C268.2 24.67,34.84 v1(24.74,34.77) ; v1(44.33,31.85) 44.46,31.71 C132.2 ; 26.85,2.29 26.84,2.28 J6.2 ; C109.2 5.21,26.06 v1(5.43,26.28) ; C378.2 11.09,27.62 v1(11.08,27.63) 10.95,27.76 C113.2 ; v1(24.95,30.26) 24.96,30.24 C254.2 ; v1(24.95,30.26) 24.75,30.46 C247.2 24.2,30.8 C256.2 ; v1(2.18,27.91) 2.15,27.88 C381.2 ; v1(26.73,34.77) 27.14,35.19 C393.2 ; C21.2 22.37,23.57 22.26,23.67 v1(22.25,23.67) ; C117.2 2.15,33.79 v1(2.18,33.76) ; C99.2 23.94,25.81 C36.2 24.21,25.84 24.3,25.75 v1(24.69,25.75) ; C118.2 9.42,35.79 v1(9.38,35.75) ; v1(26.95,30.46) 26.99,30.5 C241.2 ; C131.2 v1(45.3,36.4) ; C74.2 22.01,30.09 v1(22.01,30.21) ; v1(30.14,36.14) 30.67,35.61 R23.2 ; v1(19.7,48.82) 19.7,48.91 19.67,48.94 J4.32 ; v1(2.12,31.79) 2.04,31.7 C108.2 ; C128.2 42.96,36.08 v1(43.03,36.01) ; v1(17.95,28.24) 17.9,28.29 R4.1 ; C23.2 26.47,26.68 ; C23.2 26.09,26.3 v1(25.97,26.18) ; C374.2 11.19,24.88 v1(11.08,24.98) ; v1(14.78,48.82) 14.81,48.84 14.81,48.89 14.87,48.96 J4.8 ; v1(44.67,36.25) 44.62,36.3 C129.2 ; C112.2 6.02,31.96 v1(6.02,31.47) ; C245.2 29.14,30.41 v1(29.08,30.48) 29.37,30.77 C9.2 29.37,31.41 29.13,31.65 C391.2 ; C370.2 9.13,26.21 v1(9.34,26) ; v1(29.08,32.46) 29.41,32.46 29.72,32.14 R103.2 ; v1(6.55,30.05) 6.36,29.86 R158.1 ; C380.2 11.06,33.41 v1(11.1,33.46) 11.56,33.46 C372.2 ; C376.2 4.27,30.47 v1(3.75,30.47) 3.75,31.27 C371.2 ; v1(2.12,25.95) 2.06,26 C105.2 ; 26.47,26.68 26.59,26.8 26.59,26.79 C3.2 27.36,26.79 27.46,26.69 C17.2 ; 26.47,26.68 26.58,26.56 v1(26.58,26.2) 26.58,26.03 26.2,25.66 C6.2 26.03,25.24 25.95,25.16 C260.2 ; C33.2 24.31,27.71 C15.2 24.95,27.72 v1(24.95,28.19) 24.96,28.2 C255.2 24.67,28.71 24.36,29.03 C253.2 23.98,29.19 v1(23.5,29.19) 23.12,29.19 C35.2 22.77,29.03 22.46,29.34 C16.2 22.46,29.76 v1(22.01,30.21) ; C20.2 22.19,30.39 v1(22.01,30.21) ; v1(11.07,26.28) 11.12,26.33 C106.2 ; C115.2 2.04,30.57 v1(2.1,30.52) ; R29.2 v1(27.93,41.76) ; C100.2 24.71,32.71 v1(24.76,32.66) 24.77,32.66 C244.2 ; C136.2 C137.2 42.51,37.36 v1(43.47,37.36) ; v1(11.08,30.74) 11.12,30.74 11.17,30.7 C373.2 ; C94.2 19.92,32.28 v1(19.92,32.26) ; C454.2 v2(54.74,34.09) 54.6,33.95 C122.2 ; C101.2 26.61,28.28 v1(26.93,27.96) ; v1(7.74,34.38) 7.89,34.23 C114.2 8.38,33.29 C384.2 ; R121.1 6.54,33.58 v1(6.86,33.58) ; C375.2 3.81,27.95 v1(3.86,27.91) ; C392.2 28.71,25.14 29.04,24.81 v1(29.04,24.03)
  BOTTOM w0.305: v1(24.75,23.66) 24.99,23.42 C400.2 24.99,22.86 25.15,22.7 C265.2
  BOTTOM w0.381: C121.2 64.48,31.5 v2(63.68,31.5) ; v1(43.01,34.84) 42.84,34.67 C130.2 ; U5.4 44.15,39.22 v1(44.3,39.22) ; v1(46.49,35.5) 46.59,35.6 C127.2 ; v2(43.44,41.61) U5.9
  vias: v1(0.68,18.57) v1(0.71,16.94) v1(0.73,15.57) v1(0.71,14.35) v1(0.73,12.72) v1(0.66,5.99) v1(0.68,4.83) v1(0.68,3.35) v1(0.8,2.19) v1(1.04,47.82) v1(1.27,1.35) v1(1.4,44.4) v1(1.4,43.31) v1(1.53,49.1) v1(1.63,46.51) v1(2.08,0.86) v1(2.24,17.36) v1(2.25,18.94) v1(2.25,18.19) v1(2.59,44.42) v1(2.59,43.15) v1(2.94,45.79) v1(3,49.83) v1(3.28,0.74) v1(3.86,44.42) v1(3.86,43.15) v1(4.38,49.1) v1(4.46,46.53) v1(4.95,47.79) v1(5.13,44.42) v1(5.13,43.15) v1(5.76,0.68) v1(6.07,49.84) v1(6.15,46.37) v1(6.36,48.78) v1(6.36,47.51) v1(6.4,44.42) v1(6.99,49.84) v1(7.63,48.78) v1(7.63,47.51) v1(7.73,46.26) v1(7.98,49.81) v1(8.21,39.86) v1(8.3,0.68) v1(8.43,12.34) v1(8.43,11.58) v1(8.43,10.82) v1(8.43,10.06) v1(8.43,9.3) v1(8.89,49.81) v1(8.9,48.78) v1(8.9,47.51) v1(8.99,39.96) v1(9.19,12.34) v1(9.19,11.58) v1(9.19,10.82) v1(9.19,10.06) v1(9.19,9.3) v1(9.78,49.81) v1(9.75,39.9) v1(9.98,19.76) v1(9.98,19) v1(9.96,12.34) v1(9.96,11.58) v1(9.96,10.82) v1(9.96,10.06) v1(9.96,9.3) v1(10.17,48.78) v1(10.69,49.81) v1(10.74,19.76) v1(10.74,19) v1(10.72,12.34) v1(10.72,11.58) v1(10.72,10.82) v1(10.72,10.06) v1(10.72,9.3) v1(10.84,0.68) v1(11.48,40.36) v1(11.5,19.76) v1(11.5,19) v1(11.48,12.34) v1(11.48,11.58) v1(11.48,10.82) v1(11.48,10.06) v1(11.48,9.3) v1(13.44,0.67) v1(13.77,44.42) v1(14.33,7.71) v1(14.84,44.42) v1(15.52,30.23) v1(15.78,32.79) v1(15.97,44.47) v1(15.98,0.67) v1(17.17,44.47) v1(17.75,36.72) v1(18.34,38.05) v1(18.41,44.49) v1(18.52,0.67) v1(19.44,44.48) v1(19.68,26.03) v1(20.4,26.01) v1(20.78,44.48) v1(21.02,26.25) v1(21.06,0.66) v1(21.68,1.99) v1(22.05,44.49) v1(23.29,44.49) v1(23.6,0.66) v1(24.51,44.49) v1(26.14,0.66) v1(28.68,0.74) v1(30.63,44.48) v1(31.22,0.74) v1(33.76,0.74) v1(34.6,47.38) v1(35.68,11.22) v1(35.79,32.73) v1(35.91,48.71) v1(36.3,0.74) v1(36.39,21.37) v1(36.82,48.01) v1(38.1,1.71) v1(38.84,0.74) v1(39.55,41.42) v1(39.95,2.88) v1(39.95,1.73) v1(40.32,42.61) v1(40.62,19.91) v1(41.22,48.77) v1(41.22,2.88) v1(41.38,0.74) v1(41.49,17.55) v1(42.37,14.01) v1(42.51,17.75) v1(42.45,3.48) v1(42.49,1.73) v1(42.62,15.85) v1(43.05,19.42) v1(43.42,23.29) v1(43.56,49.56) v1(43.56,48.29) v1(43.56,47.02) v1(43.57,4.84) v1(43.57,2.3) v1(43.59,0.73) v1(43.89,15.85) v1(43.89,14.58) v1(43.88,3.37) v1(44.3,21.21) v1(44.42,11.39) v1(44.42,10.12) v1(44.39,9.09) v1(44.39,7.93) v1(44.39,6.66) v1(44.63,17.95) v1(44.63,16.68) v1(44.72,3.57) v1(44.72,2.3) v1(44.83,49.56) v1(44.83,48.29) v1(44.83,47.02) v1(45.28,4.93) v1(45.64,0.84) v1(45.69,11.39) v1(45.69,10.12) v1(45.66,9.09) v1(45.66,7.93) v1(45.66,6.66) v1(45.84,47.81) v1(45.84,2.96) v1(45.9,17.95) v1(45.9,16.68) v1(46.33,49.08) v1(46.33,4.24) v1(46.43,46.5) v1(46.43,1.65) v1(46.67,19.82) v1(46.67,18.55) v1(46.98,14.49) v1(46.98,13.22) v1(46.98,11.95) v1(46.98,10.68) v1(46.95,9.65) v1(46.95,8.5) v1(46.95,7.23) v1(46.95,5.96) v1(47.22,21.95) v1(47.54,24.53) v1(47.74,45.77) v1(47.69,19.86) v1(47.69,18.59) v1(47.74,0.93) v1(47.8,49.82) v1(47.8,4.97) v1(48.22,9.65) v1(48.22,8.5) v1(48.22,7.23) v1(48.22,5.96) v1(48.25,14.49) v1(48.25,13.22) v1(48.25,11.95) v1(48.25,10.68) v1(49.18,49.08) v1(49.18,4.24) v1(49.26,46.52) v1(49.34,27.11) v1(49.26,1.67) v1(49.52,14.49) v1(49.52,13.22) v1(49.52,11.95) v1(49.52,10.68) v1(49.49,9.65) v1(49.49,8.5) v1(49.49,7.23) v1(49.49,5.96) v1(49.75,47.77) v1(49.75,2.93) v1(49.79,41.97) v1(50.27,43.49) v1(50.39,0.89) v1(50.94,49.49) v1(50.94,48.22) v1(50.94,46.95) v1(50.94,45.68) v1(50.94,40.87) v1(51.34,5.22) v1(51.43,42.04) v1(51.45,3.55) v1(51.43,2.17) v1(51.59,43.48) v1(51.91,0.89) v1(52.06,40.81) v1(52.21,49.49) v1(52.21,48.22) v1(52.21,46.95) v1(52.21,45.68) v1(52.61,5.22) v1(52.72,3.55) v1(52.7,2.17) v1(53.22,42.03) v1(53.27,43.48) v1(53.44,0.89) v1(53.48,49.49) v1(53.48,48.22) v1(53.48,46.95) v1(53.48,45.68) v1(53.88,5.22) v1(53.99,3.55) v1(53.97,2.17) v1(54.75,49.49) v1(54.75,48.22) v1(54.75,46.95) v1(54.75,45.68) v1(54.92,5.19) v1(55.02,3.53) v1(55.01,2.14) v1(54.96,0.89) v1(56.02,49.49) v1(56.02,48.22) v1(56.02,46.95) v1(56.02,45.68) v1(56.01,44.51) v1(56.07,5.19) v1(56.18,3.53) v1(56.16,2.14) v1(56.48,0.89) v1(56.75,41.1) v1(56.87,42.53) v1(57.29,49.49) v1(57.29,48.22) v1(57.29,46.95) v1(57.29,45.68) v1(57.28,44.51) v1(57.31,5.25) v1(57.42,3.58) v1(57.4,2.2) v1(57.51,42.53) v1(58.01,0.89) v1(58.47,5.25) v1(58.56,49.49) v1(58.56,48.22) v1(58.56,46.95) v1(58.56,45.68) v1(58.55,44.51) v1(58.57,3.58) v1(58.55,2.2) v1(59.38,0.89) v1(59.47,5.16) v1(59.57,3.5) v1(59.56,2.11) v1(59.83,49.49) v1(59.83,48.22) v1(59.83,46.95) v1(59.83,45.68) v1(59.81,44.36) v1(59.81,43.09) v1(60.74,5.16) v1(60.84,3.5) v1(60.83,2.11) v1(60.91,0.89) v1(61.1,49.49) v1(61.1,48.22) v1(61.1,46.95) v1(61.1,45.68) v1(61.08,44.36) v1(61.08,43.09) v1(62.01,5.16) v1(62.11,3.5) v1(62.1,2.11) v1(62.35,43.09) v1(62.4,48.2) v1(62.4,46.93) v1(62.4,45.66) v1(62.4,44.39) v1(62.43,0.89) v1(62.48,49.45) v1(63.05,5.14) v1(63.14,2.08) v1(63.15,3.47) v1(63.34,29.85) v1(63.6,43.06) v1(63.6,41.79) v1(63.6,40.52) v1(63.67,48.2) v1(63.67,46.93) v1(63.67,45.66) v1(63.67,44.39) v1(63.74,0.91) v1(63.75,49.45) v1(64.2,5.14) v1(64.3,3.47) v1(64.29,2.08) v1(64.63,24) v1(64.64,22.88) v1(64.94,48.2) v1(64.94,46.93) v1(64.94,45.66) v1(64.94,44.39) v1(64.87,43.06) v1(64.87,41.79) v1(64.87,40.52) v1(65.02,49.45) v1(65.04,0.85) v1(65.57,39.62) v1(65.57,38.35) v1(65.75,22.87) v1(65.91,24.31) v1(66.14,44.33) v1(66.14,43.06) v1(66.14,41.79) v1(66.14,40.52) v1(66.18,49.49) v1(66.18,48.22) v1(66.18,46.95) v1(66.18,45.68) v1(66.2,26.58) v1(66.19,1.22) v1(66.84,39.62) v1(66.84,38.35) v1(66.79,27.71) v1(67.03,29.04) v1(67.03,26.5) v1(67.05,23.25) v1(67.07,37.17) v1(67.07,30.39) v1(67.11,24.25) v1(67.15,1.25) v1(67.41,44.33) v1(67.41,43.06) v1(67.41,41.79) v1(67.41,40.52) v1(67.45,49.49) v1(67.45,48.22) v1(67.45,46.95) v1(67.45,45.68) v1(67.53,16.39) v1(67.54,15.5) v1(67.54,11.28) v1(67.54,7.47) v1(67.57,21.86) v1(67.57,20.9) v1(67.56,19.74) v1(67.56,18.72) v1(67.56,17.47) v1(67.56,14.32) v1(67.55,13.4) v1(67.56,12.39) v1(67.55,9.94) v1(67.55,8.63) v1(67.56,6.28) v1(68.11,39.62) v1(68.11,38.35) v1(68.06,27.71) v1(68.18,2.36) v1(68.31,48.03) v1(68.31,46.76) v1(68.27,45.06) v1(68.27,43.79) v1(68.27,42.32) v1(68.27,41.05) v1(68.32,35.19) v1(68.32,33.92) v1(68.32,32.65) v1(68.34,31.66) v1(68.34,30.39) v1(68.3,29.04) v1(68.3,26.5) v1(68.36,36.53) v1(68.6,21.92) v1(68.61,20.66) v1(68.58,19.52) v1(68.58,18.4) v1(68.61,16.98) v1(68.57,15.72) v1(68.6,14.58) v1(68.59,13.38) v1(68.59,12.38) v1(68.59,11.2) v1(68.58,9.96) v1(68.6,8.77) v1(68.6,7.41) v1(68.6,6.1) v1(68.61,4.85) v2(7.31,5.08) v2(7.29,4.32) v2(7.26,3.45) v2(17.4,8.58) v2(17.91,7.72) v2(18.41,9.68) v2(18.39,8.64) v2(23.93,5.04) v2(23.93,4.4) v2(24.1,10.53) v2(24.1,9.9) v2(24.56,5.04) v2(24.56,4.4) v2(25.2,5.04) v2(25.2,4.4) v2(25.37,10.53)
